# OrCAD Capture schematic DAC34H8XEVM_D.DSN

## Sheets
1 SH1 - DAC: size B; title: DAC34H8X EVM; rev: D; note: DAC
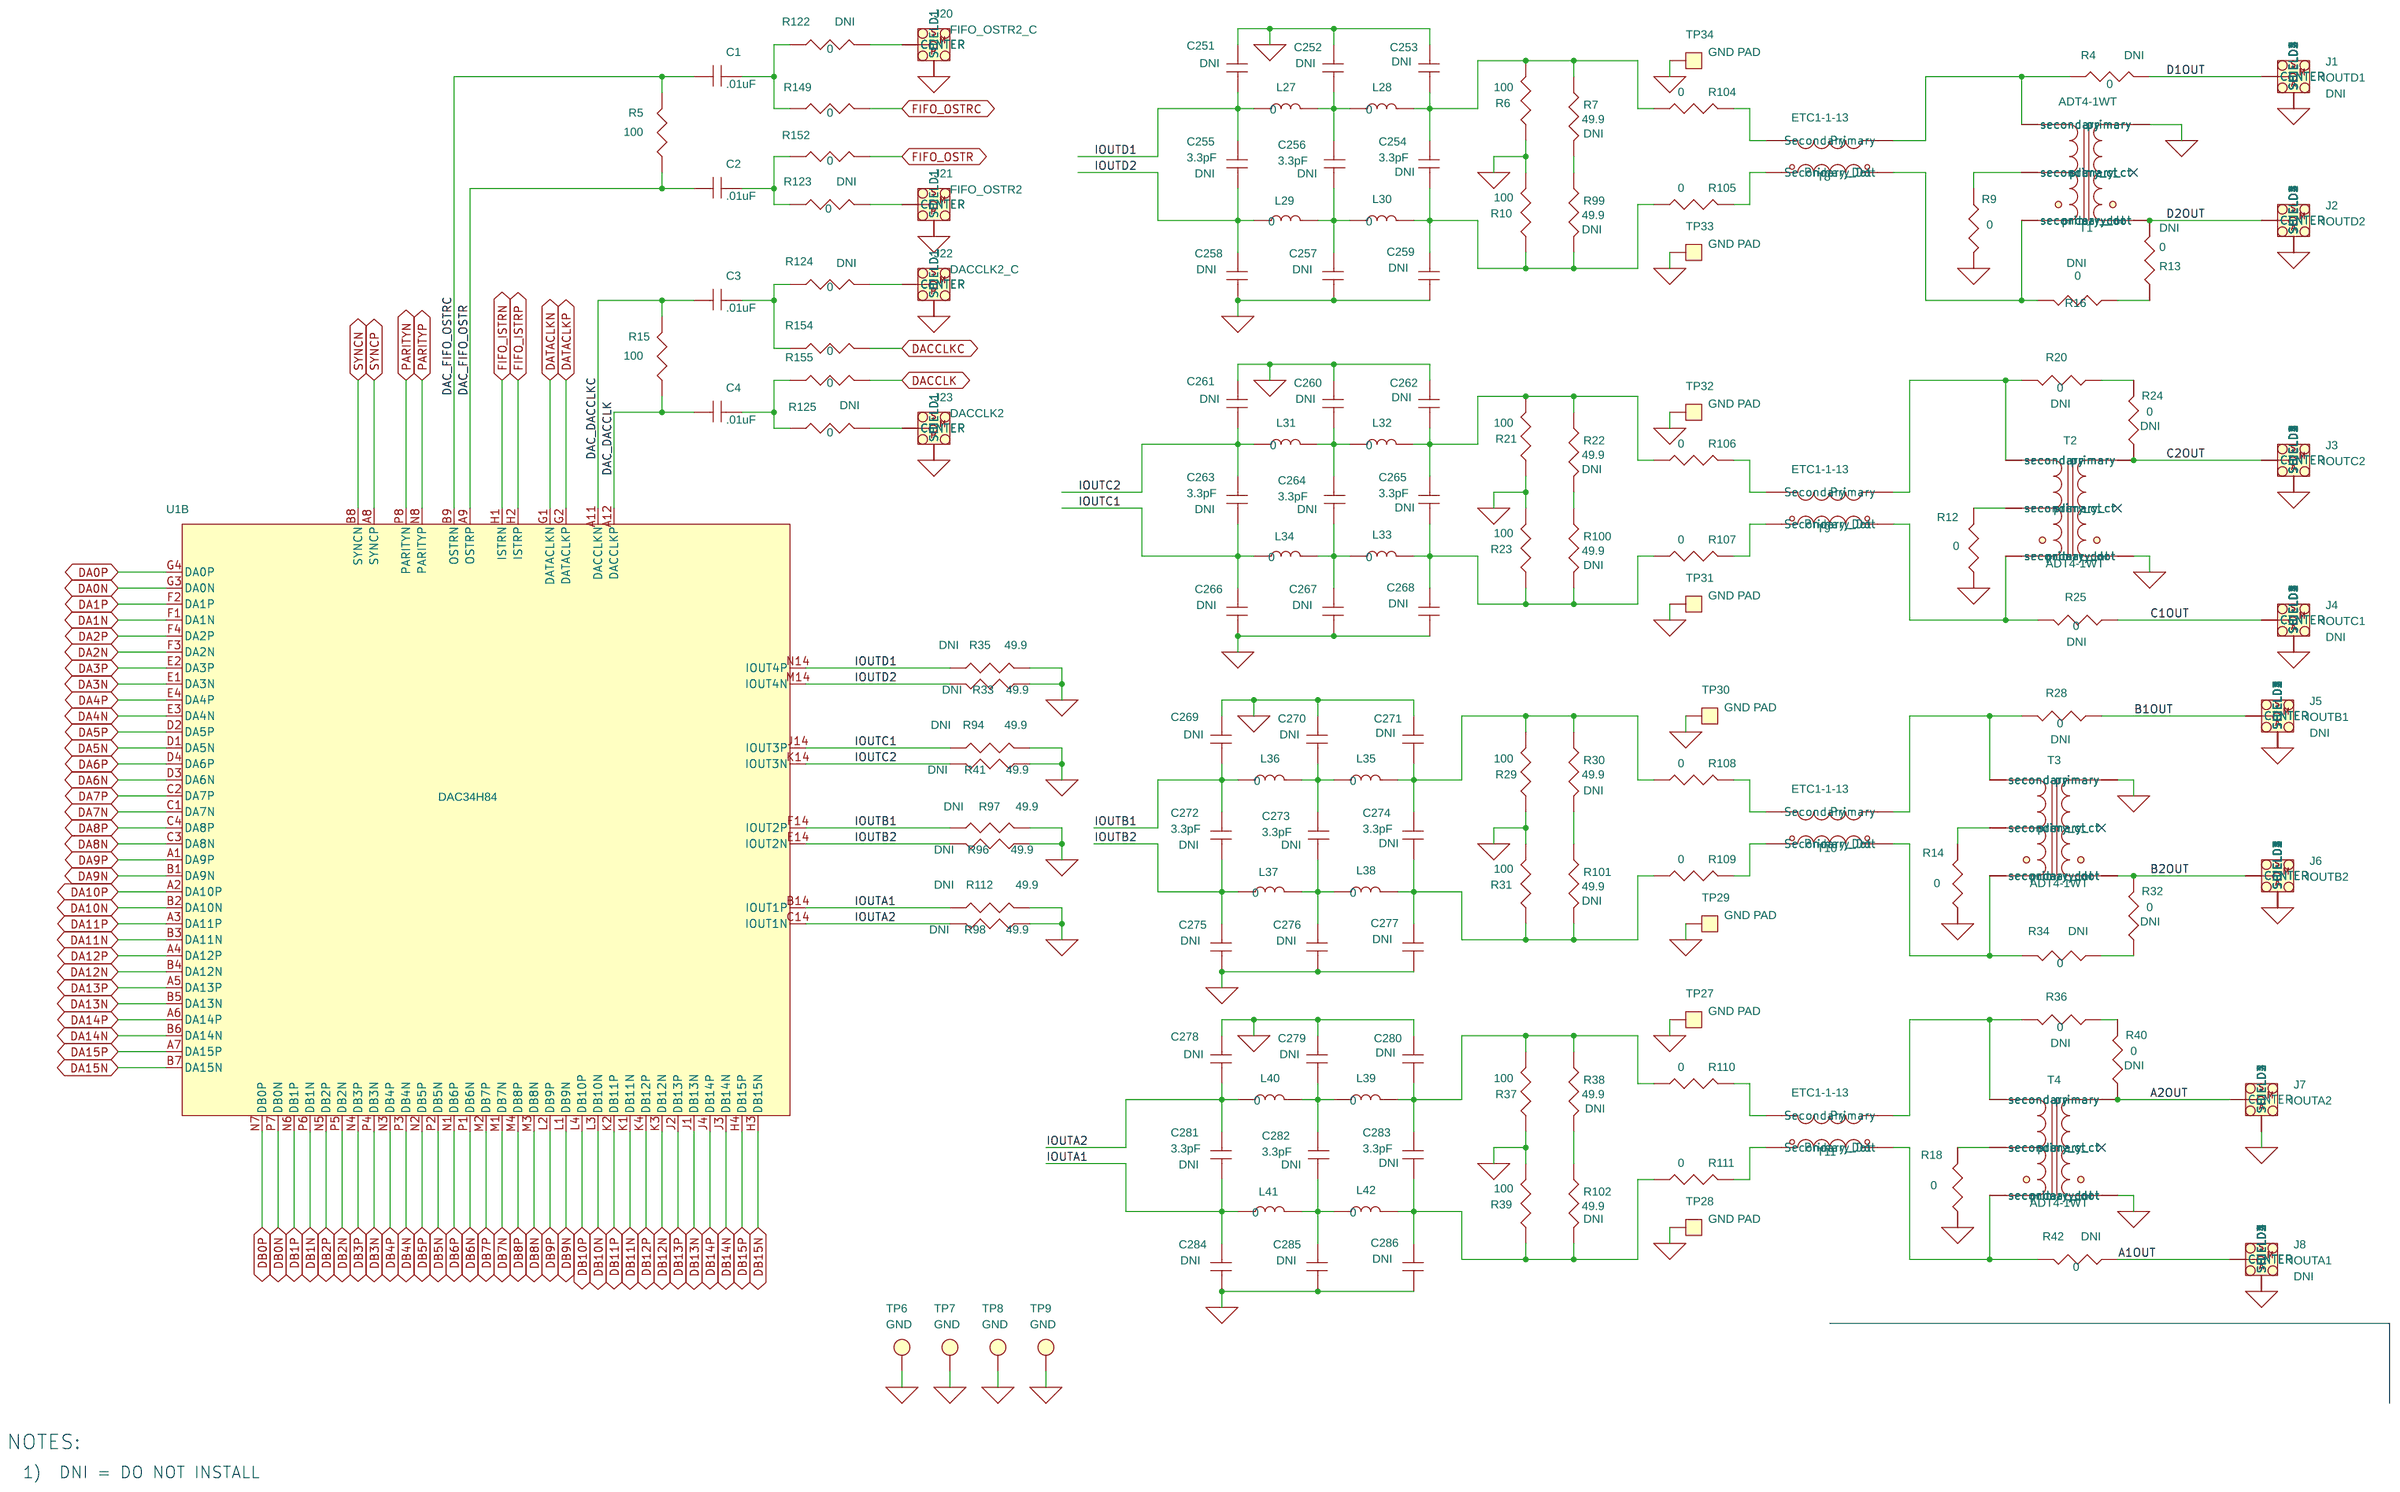
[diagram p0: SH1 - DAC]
2 SH2 - DAC: size B
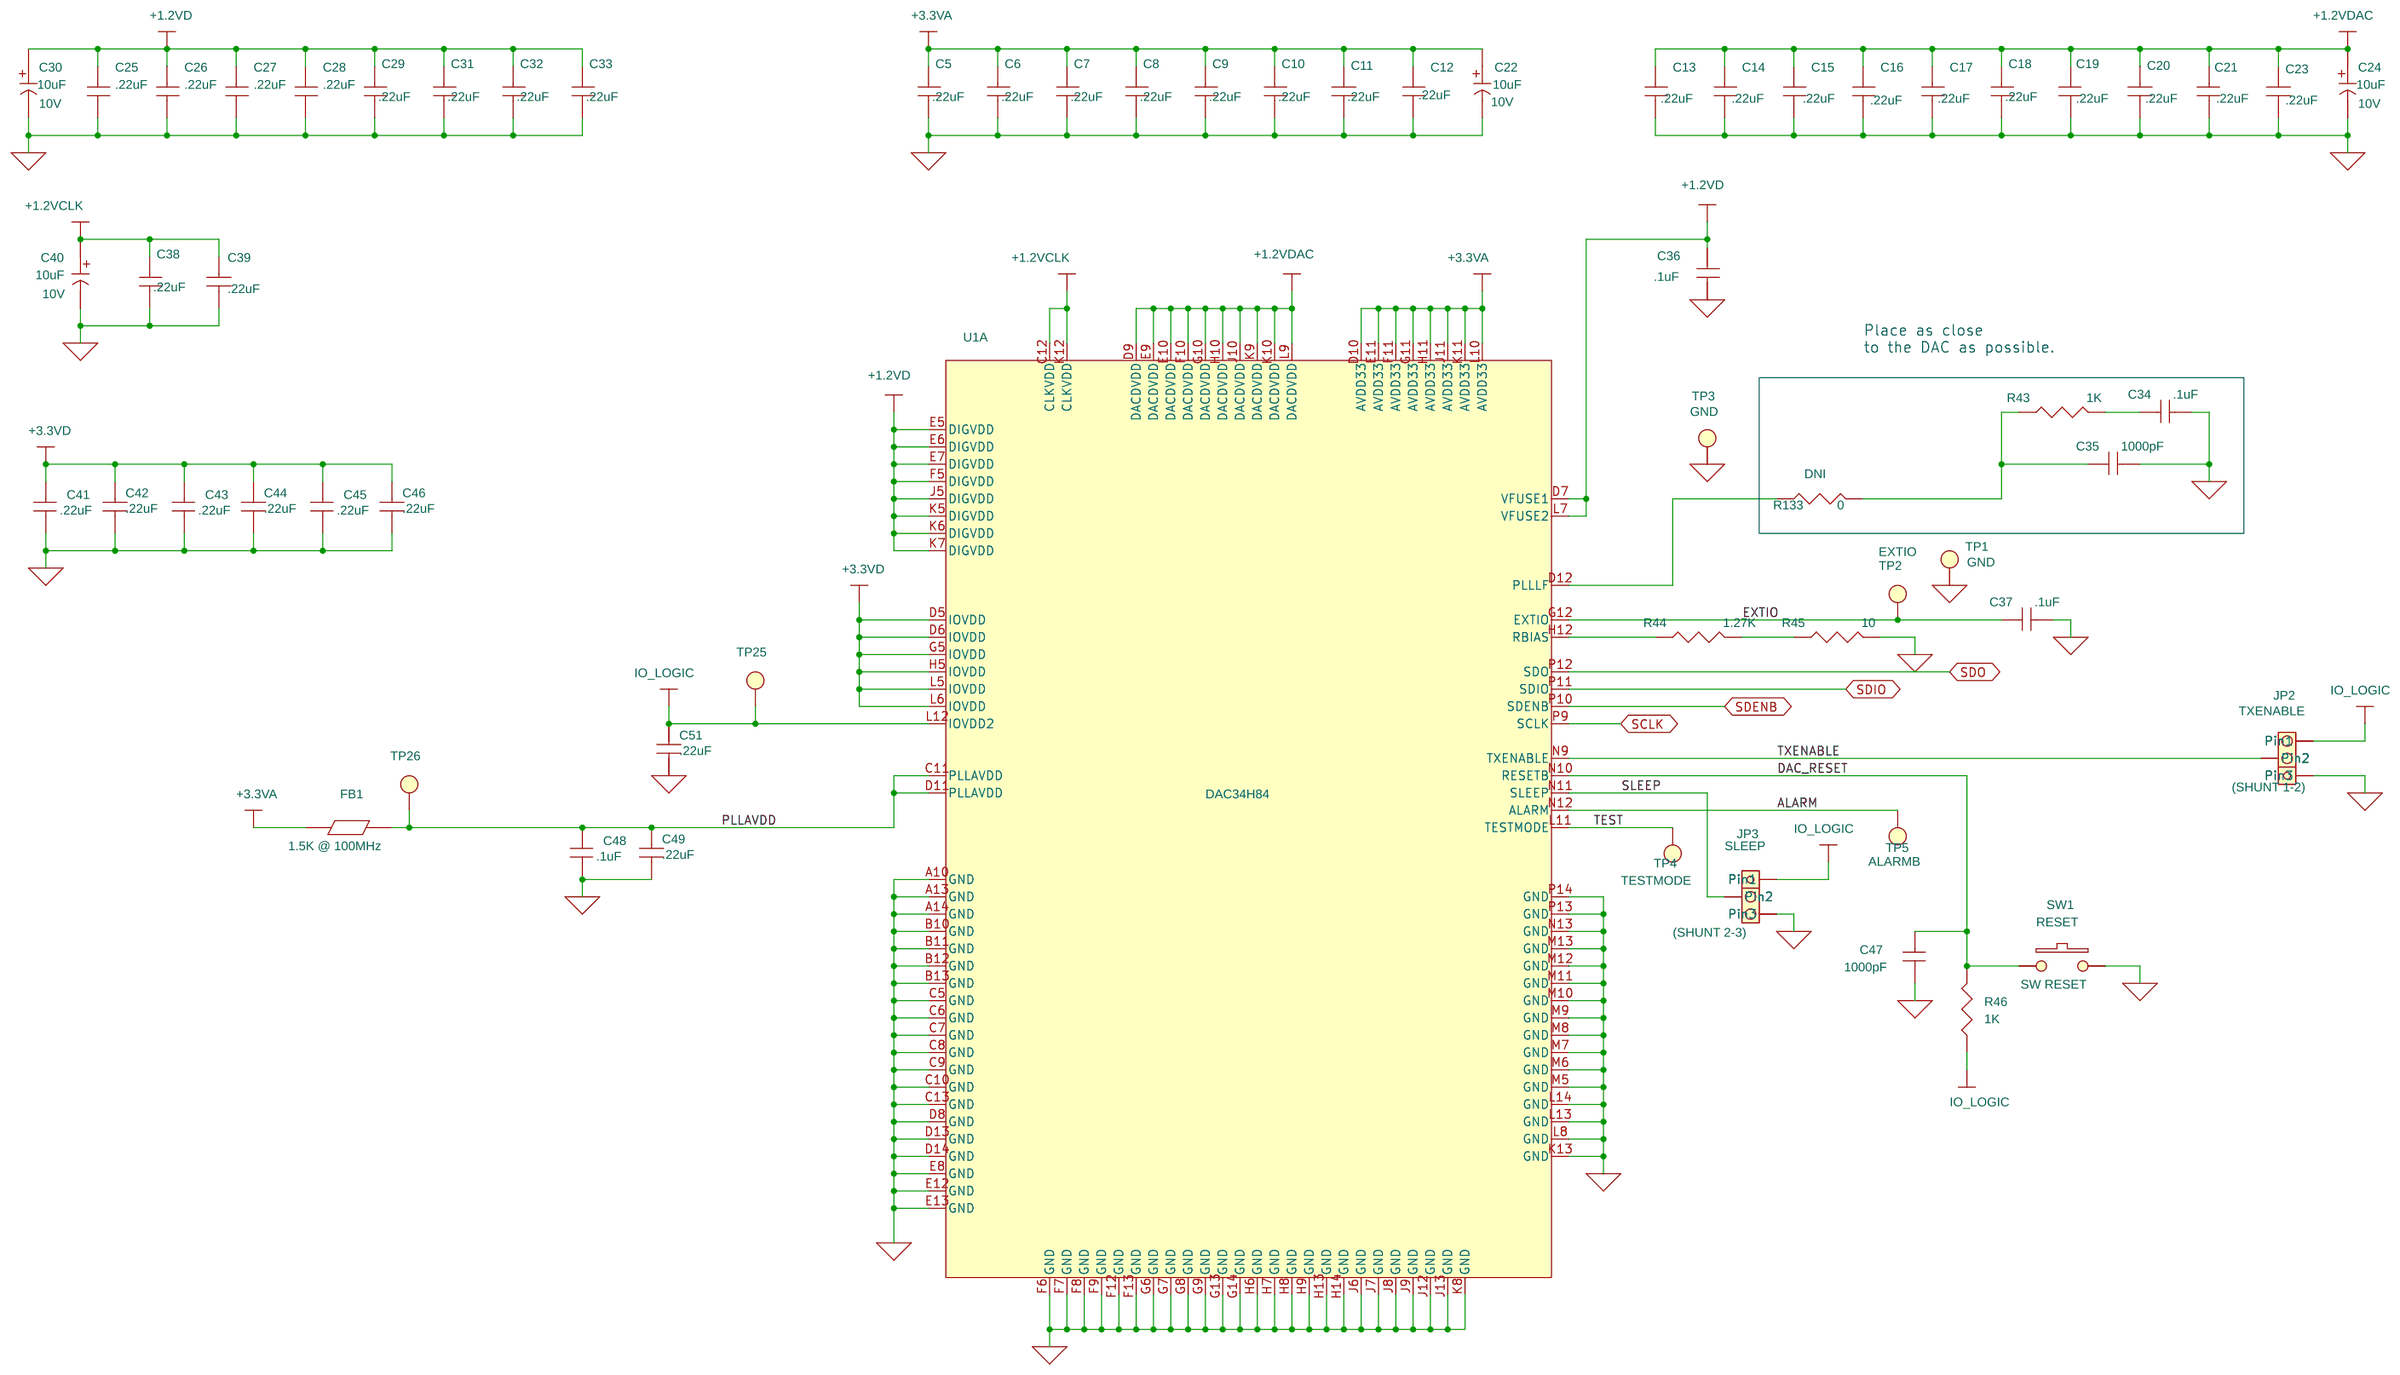
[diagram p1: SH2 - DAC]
3 SH3 - CDC: size B; note: CDC
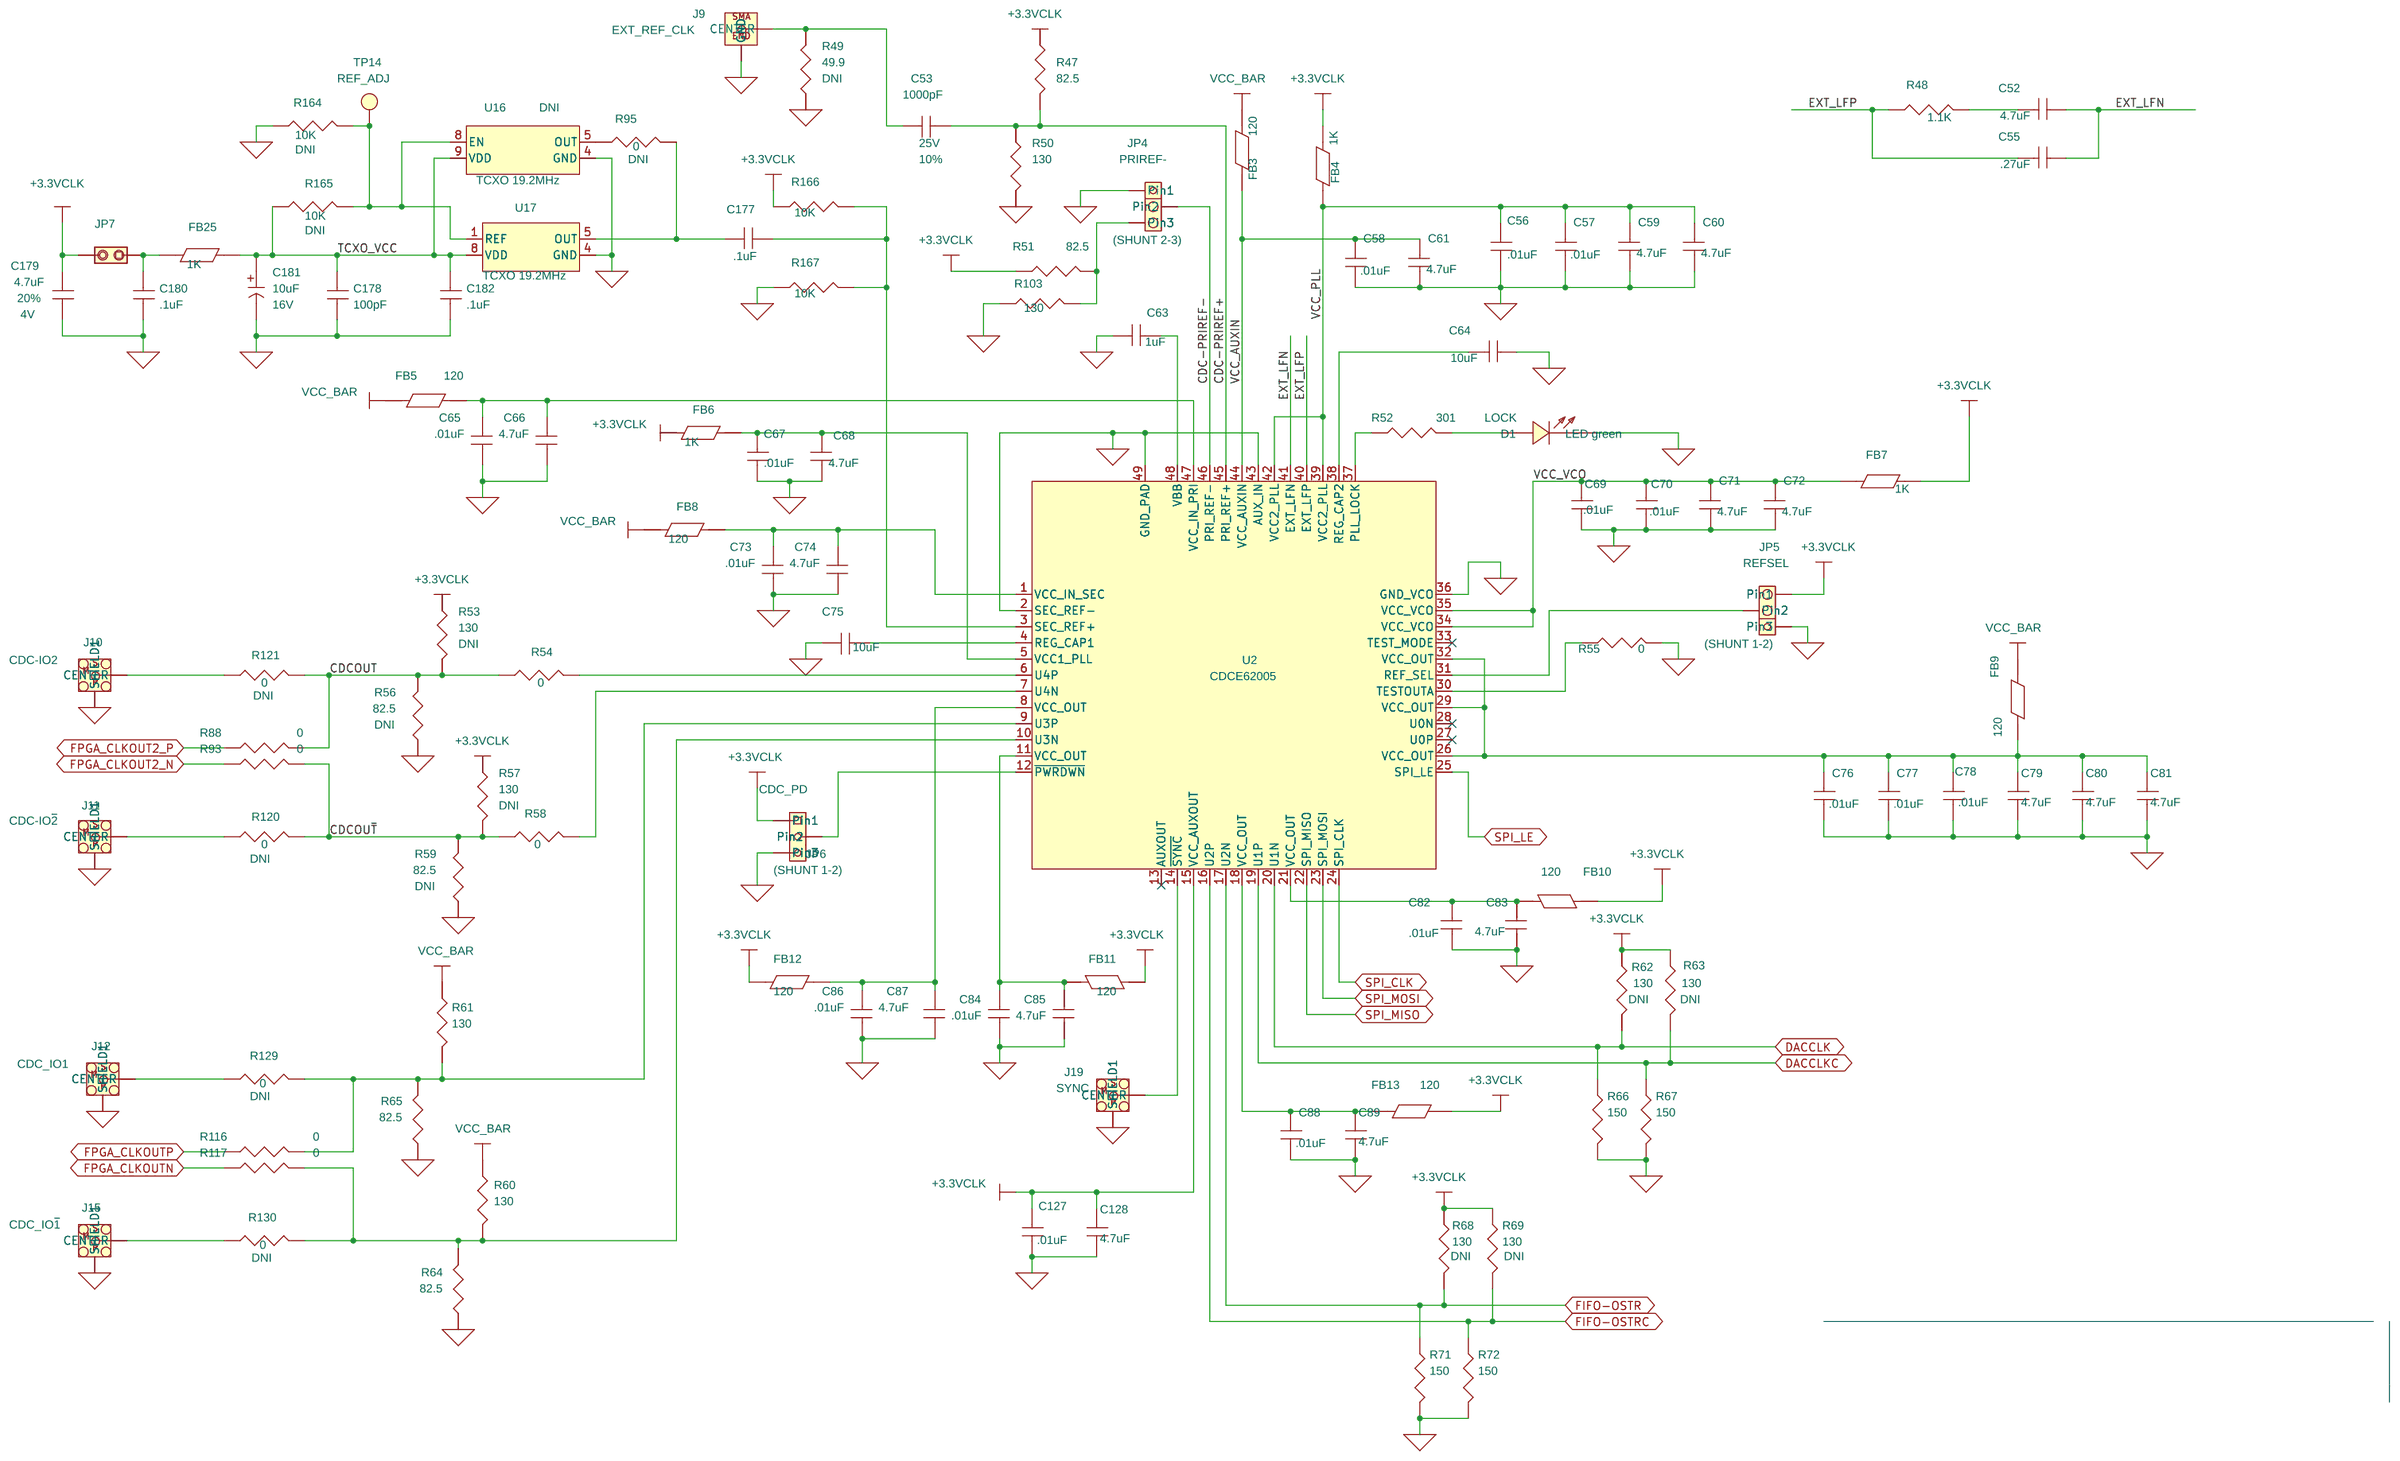
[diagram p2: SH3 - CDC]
4 SH4 - CDC2: size B; note: CDC
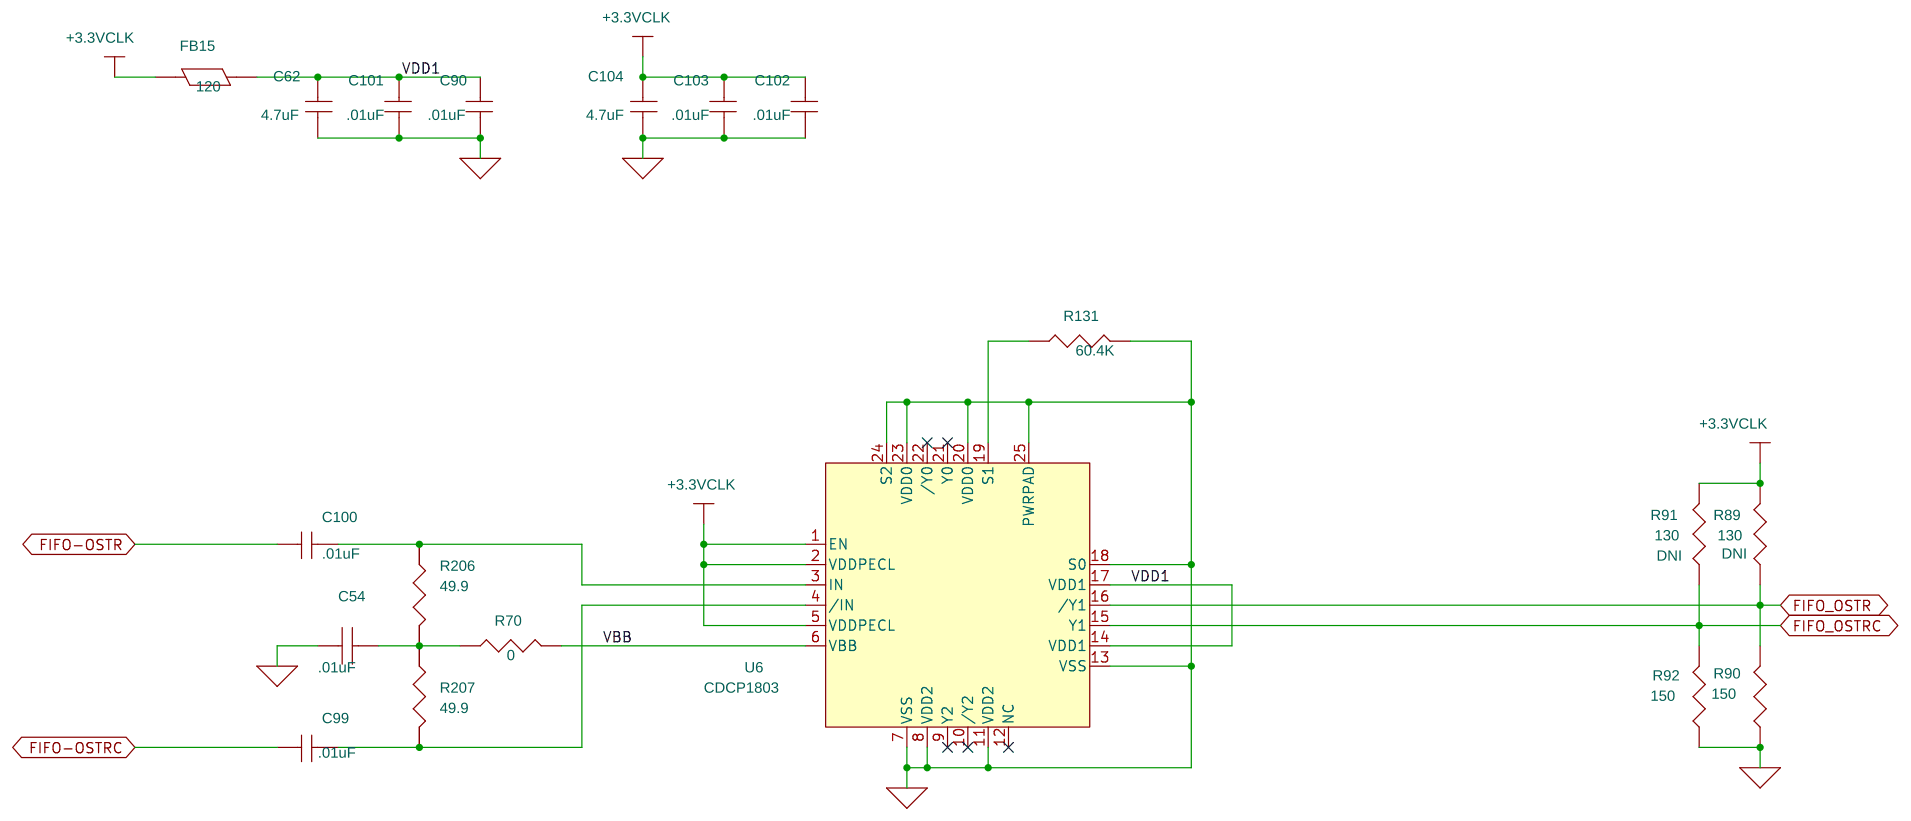
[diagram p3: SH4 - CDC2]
5 SH5 - INTERFACE CONTROL: size B; note: INTERFACE
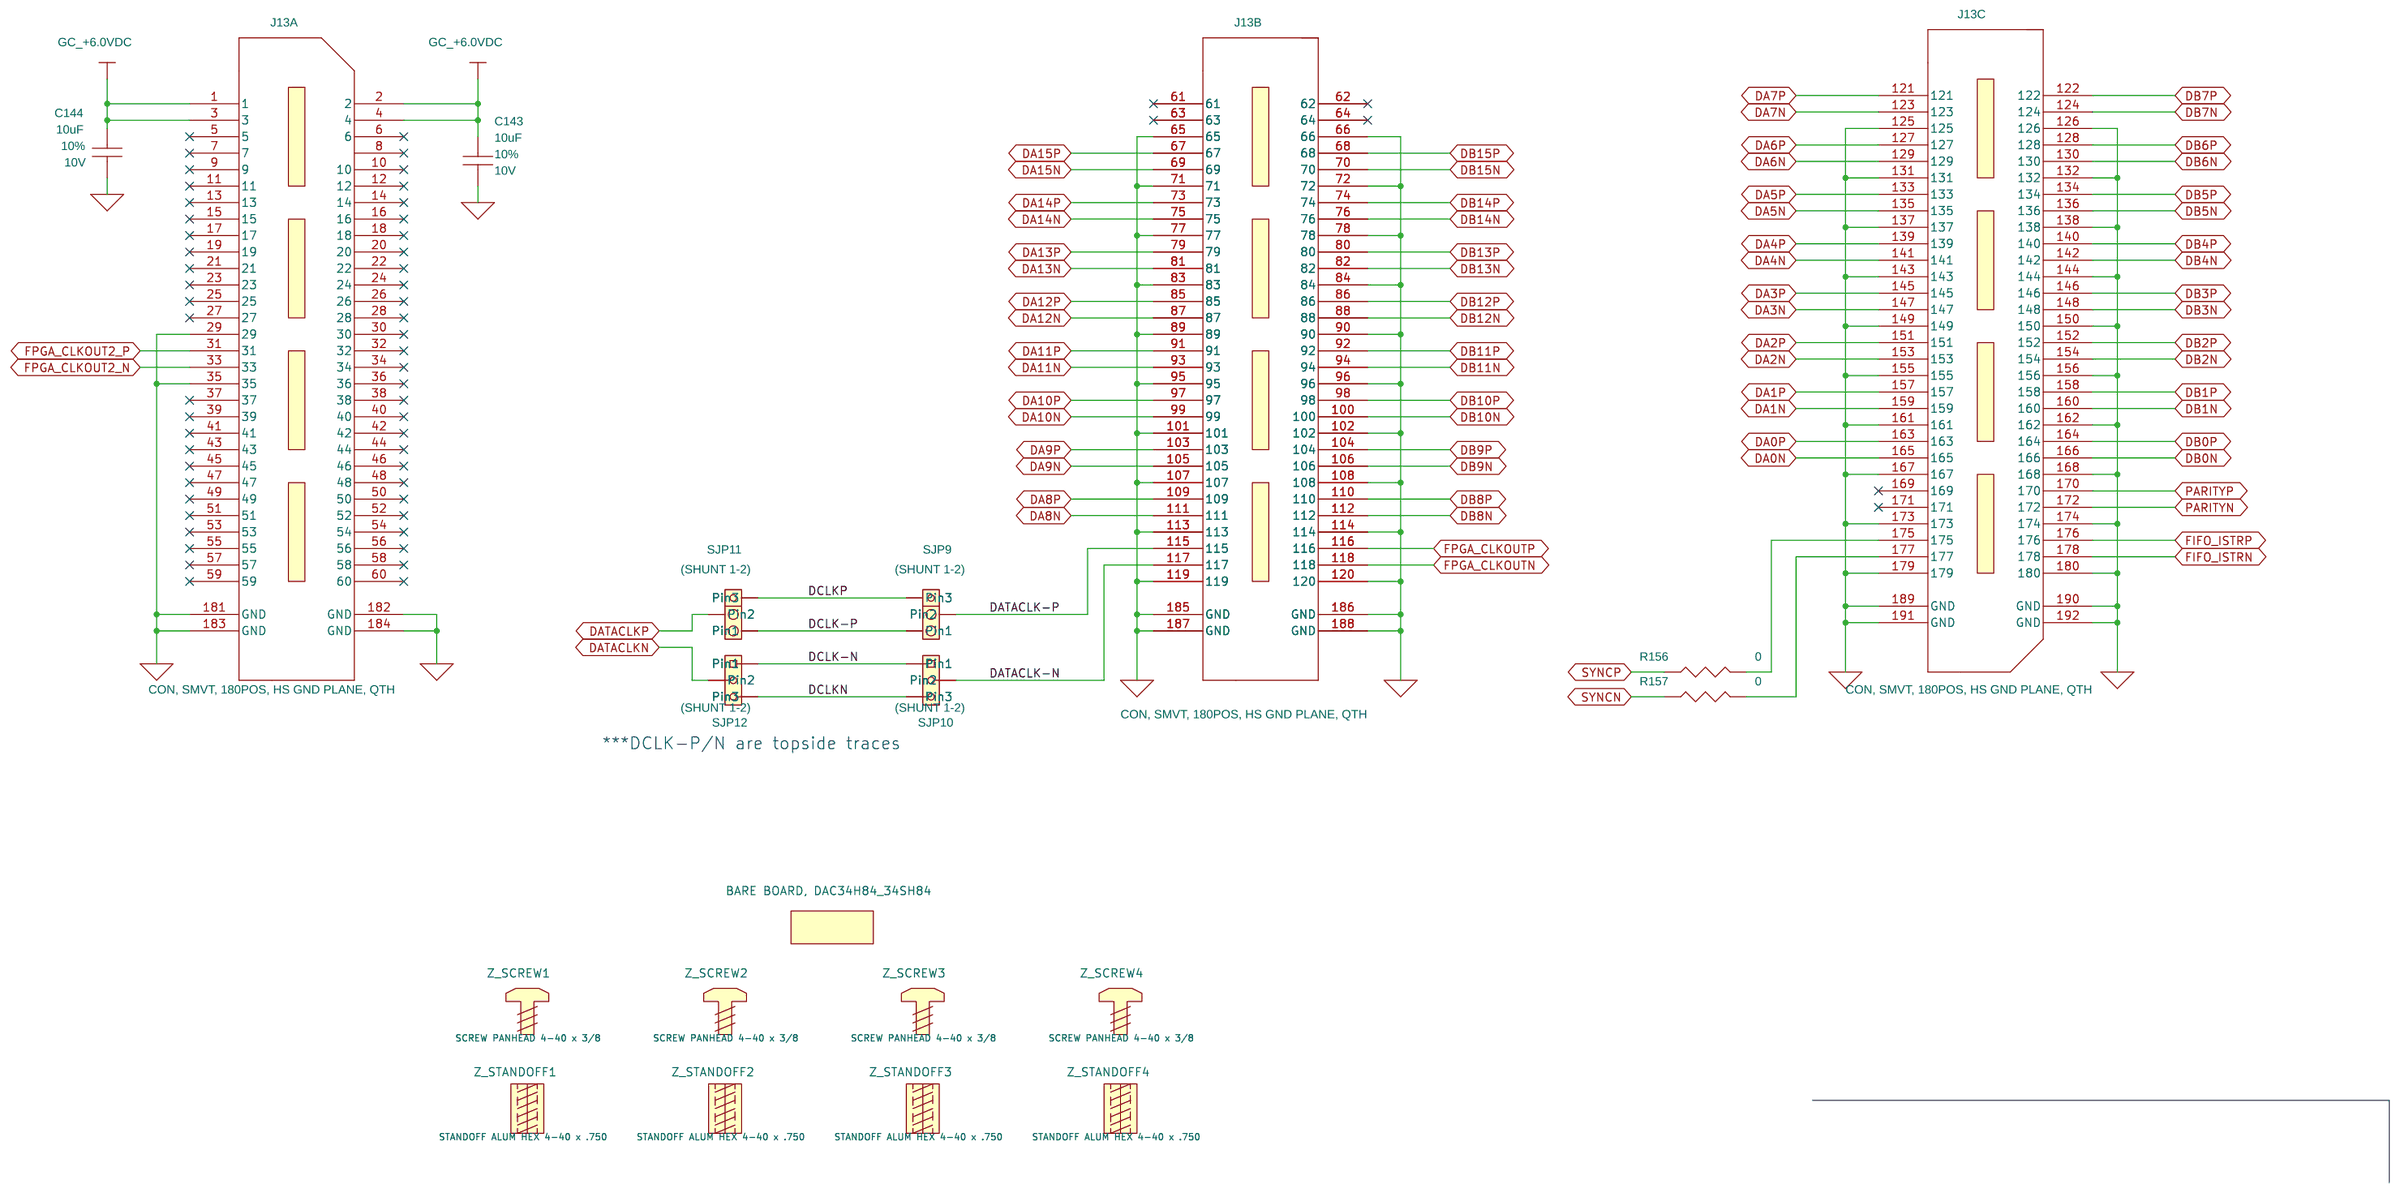
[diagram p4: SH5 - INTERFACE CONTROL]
6 SH6 - USB INTERFACE: size B; note: USB
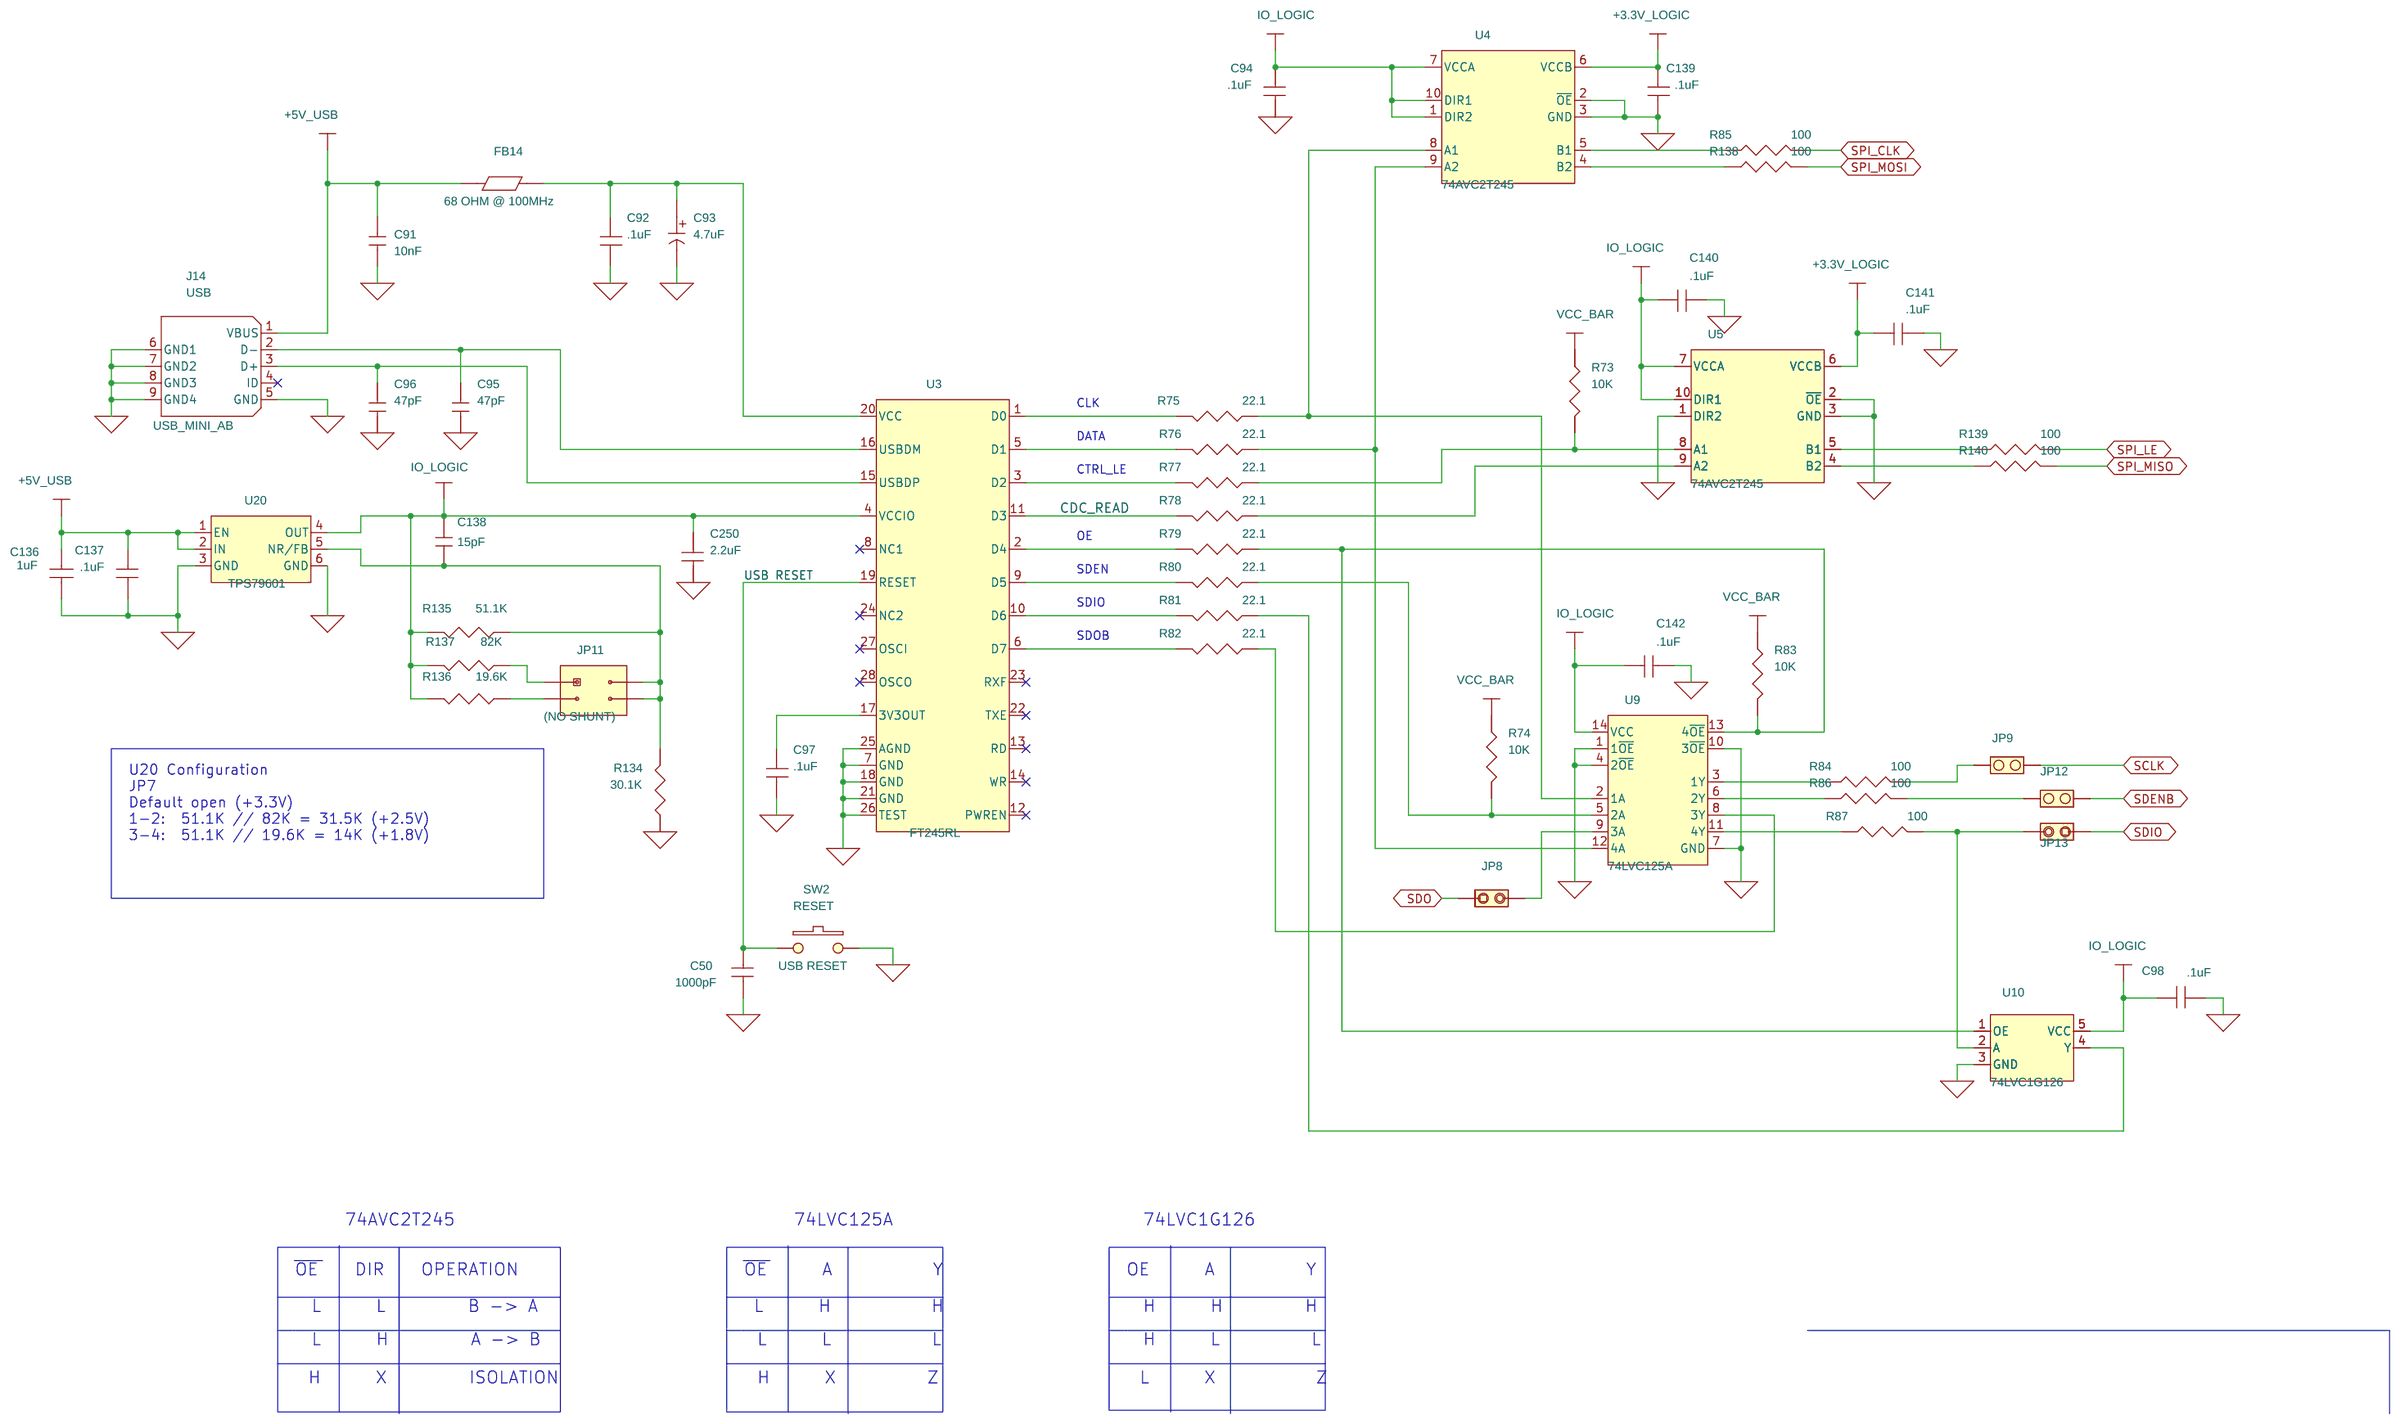
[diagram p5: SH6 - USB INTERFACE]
7 SH7 - POWER DISTRIBUTION: size B
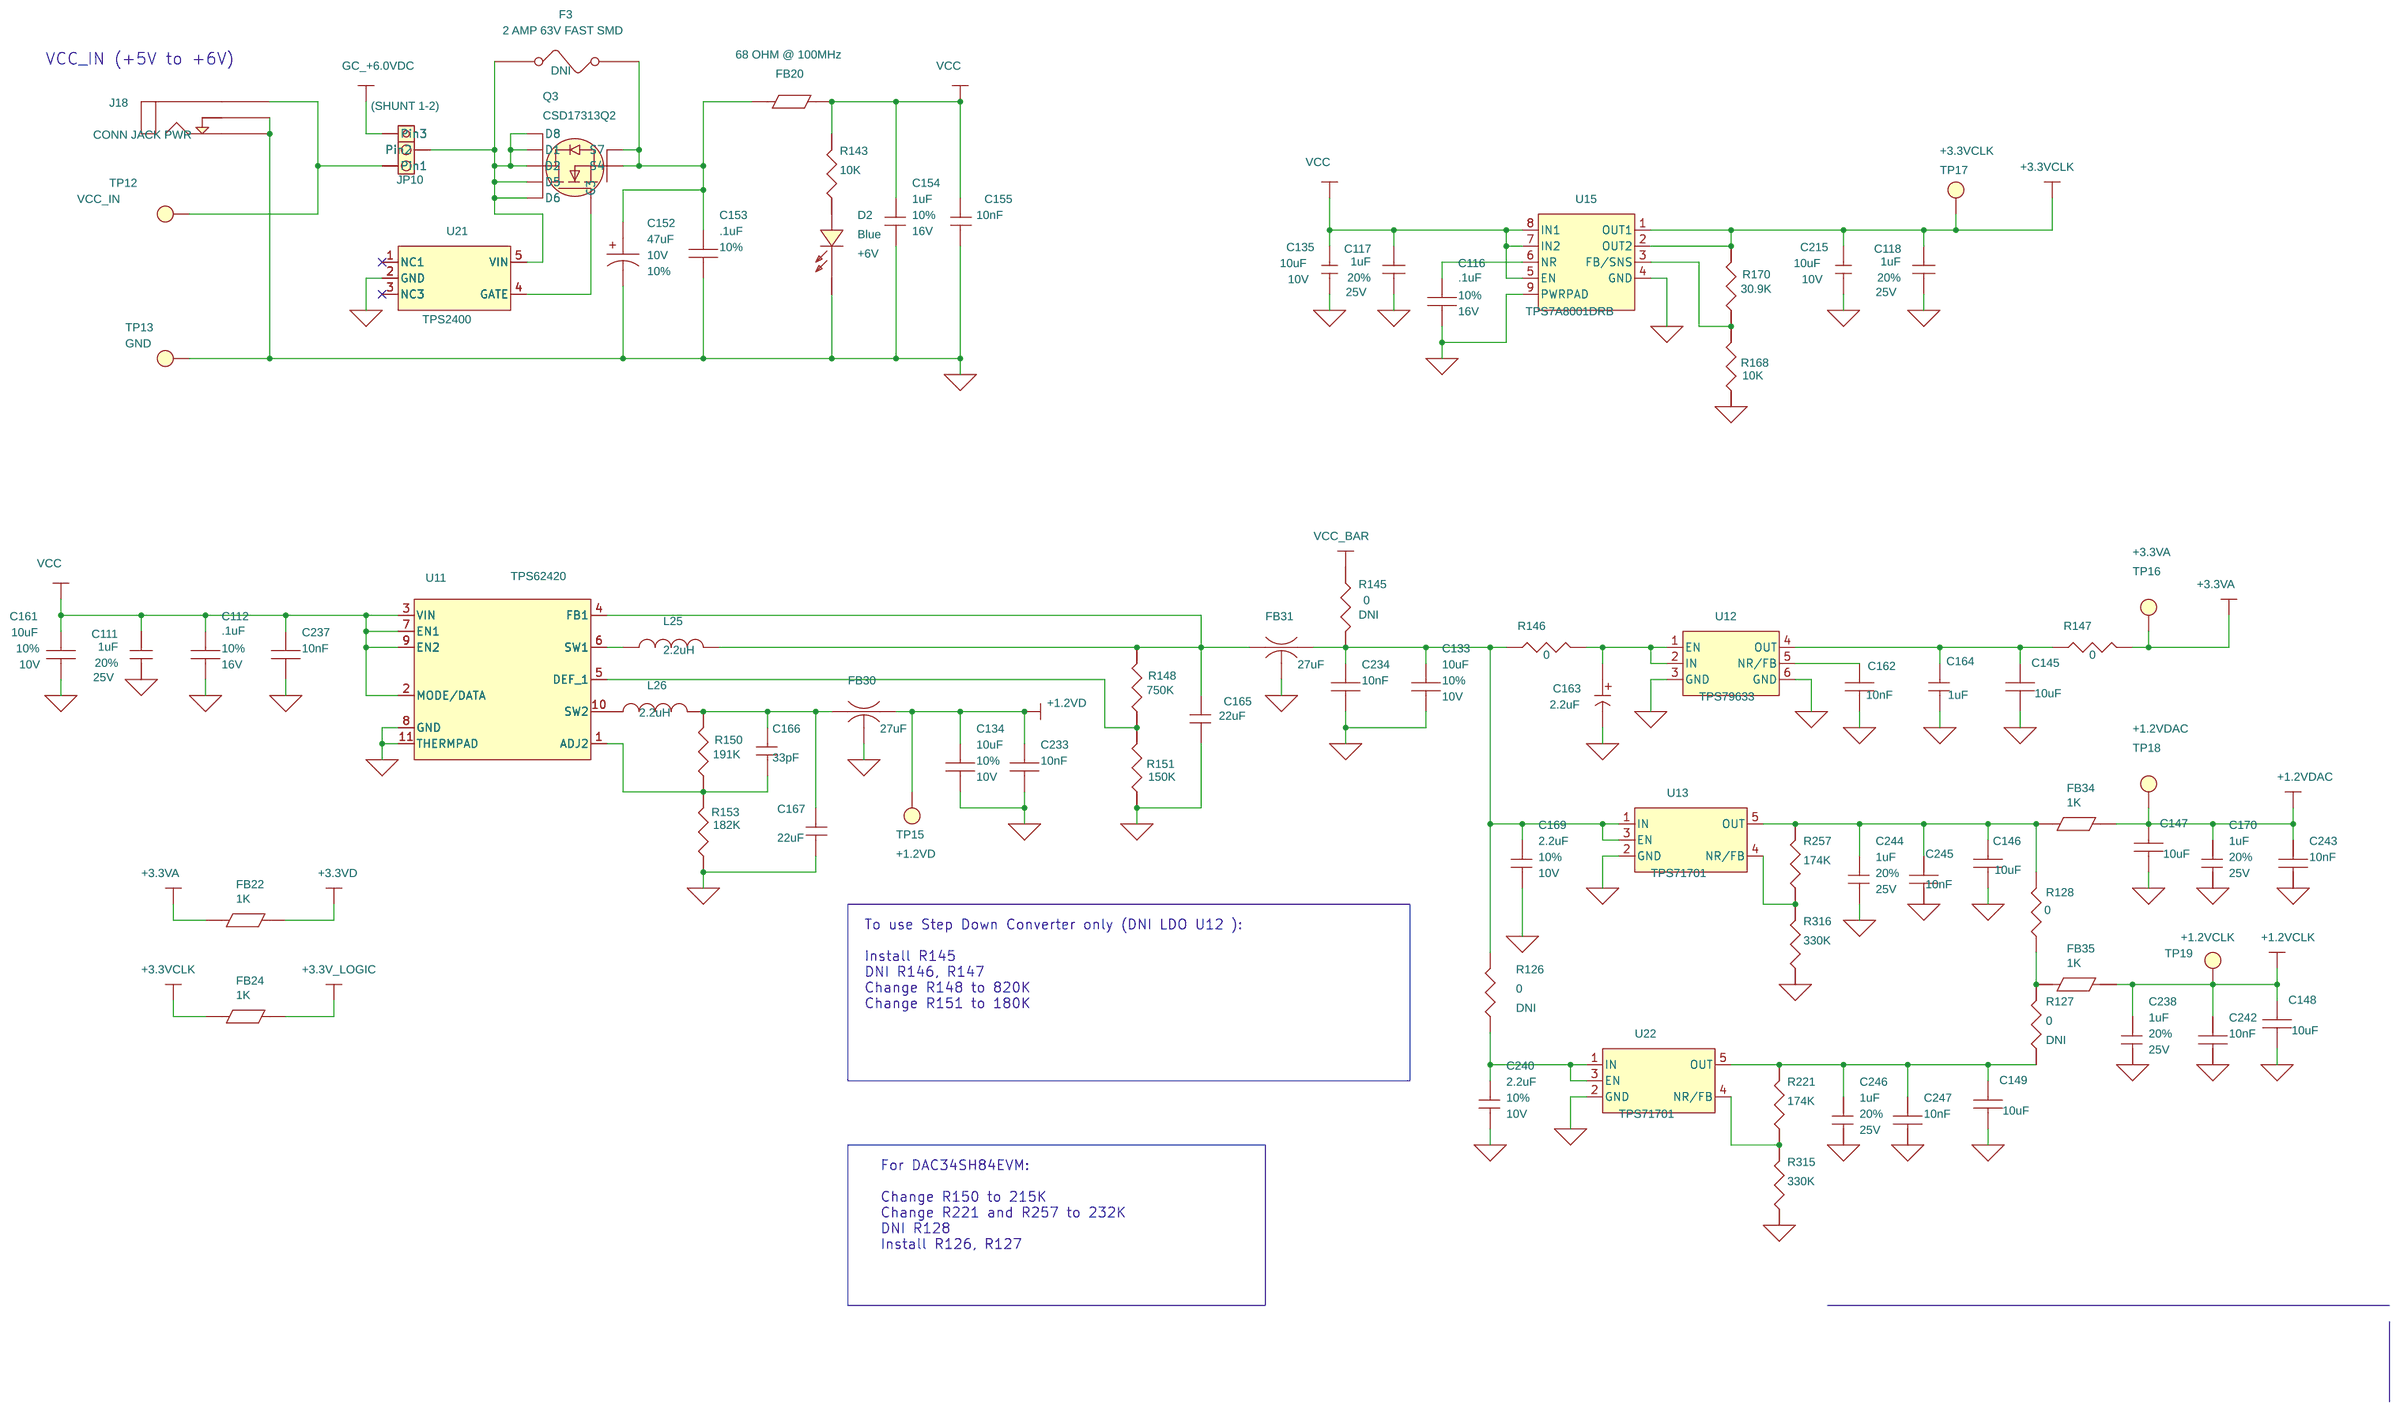
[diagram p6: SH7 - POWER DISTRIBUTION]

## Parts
sheet SH1 - DAC
C1  .01uF  [0402]
C2  .01uF  [0402]
C3  .01uF  [0402]
C4  .01uF  [0402]
C251  CAP NP_1  [0402]
C252  CAP NP_1  [0402]
C253  CAP NP_1  [0402]
C254  3.3pF  [0402]
C255  3.3pF  [0402]
C256  3.3pF  [0402]
C257  CAP NP_1  [0402]
C258  CAP NP_1  [0402]
C259  CAP NP_1  [0402]
C260  CAP NP_1  [0402]
C261  CAP NP_1  [0402]
C262  CAP NP_1  [0402]
C263  3.3pF  [0402]
C264  3.3pF  [0402]
C265  3.3pF  [0402]
C266  CAP NP_1  [0402]
C267  CAP NP_1  [0402]
C268  CAP NP_1  [0402]
C269  CAP NP_1  [0402]
C270  CAP NP_1  [0402]
C271  CAP NP_1  [0402]
C272  3.3pF  [0402]
C273  3.3pF  [0402]
C274  3.3pF  [0402]
C275  CAP NP_1  [0402]
C276  CAP NP_1  [0402]
C277  CAP NP_1  [0402]
C278  CAP NP_1  [0402]
C279  CAP NP_1  [0402]
C280  CAP NP_1  [0402]
C281  3.3pF  [0402]
C282  3.3pF  [0402]
C283  3.3pF  [0402]
C284  CAP NP_1  [0402]
C285  CAP NP_1  [0402]
C286  CAP NP_1  [0402]
J1  SMA_PCB_THVT  [SMA_THVT_312x312]
J2  SMA_PCB_THVT  [SMA_THVT_312x312]
J3  SMA_PCB_THVT  [SMA_THVT_312x312]
J4  SMA_PCB_THVT  [SMA_THVT_312x312]
J5  SMA_PCB_THVT  [SMA_THVT_312x312]
J6  SMA_PCB_THVT  [SMA_THVT_312x312]
J7  SMA_PCB_THVT  [SMA_THVT_312x312]
J8  SMA_PCB_THVT  [SMA_THVT_312x312]
J20  SMP_PCB_SMT  [smp_b120]
J21  SMP_PCB_SMT  [smp_b120]
J22  SMP_PCB_SMT  [smp_b120]
J23  SMP_PCB_SMT  [smp_b120]
L27  0  [0402]
L28  0  [0402]
L29  0  [0402]
L30  0  [0402]
L31  0  [0402]
L32  0  [0402]
L33  0  [0402]
L34  0  [0402]
L35  0  [0402]
L36  0  [0402]
L37  0  [0402]
L38  0  [0402]
L39  0  [0402]
L40  0  [0402]
L41  0  [0402]
L42  0  [0402]
R4  0  [0402]
R5  100  [0402]
R6  100  [0402]
R7  49.9  [0402]
R9  0  [0402]
R10  100  [0402]
R12  0  [0402]
R13  0  [0402]
R14  0  [0402]
R15  100  [0402]
R16  0  [0402]
R18  0  [0402]
R20  0  [0402]
R21  100  [0402]
R22  49.9  [0402]
R23  100  [0402]
R24  0  [0402]
R25  0  [0402]
R28  0  [0402]
R29  100  [0402]
R30  49.9  [0402]
R31  100  [0402]
R32  0  [0402]
R33  49.9  [0201]
R34  0  [0402]
R35  49.9  [0201]
R36  0  [0402]
R37  100  [0402]
R38  49.9  [0402]
R39  100  [0402]
R40  0  [0402]
R41  49.9  [0201]
R42  0  [0402]
R94  49.9  [0201]
R96  49.9  [0201]
R97  49.9  [0201]
R98  49.9  [0201]
R99  49.9  [0402]
R100  49.9  [0402]
R101  49.9  [0402]
R102  49.9  [0402]
R104  0  [0402]
R105  0  [0402]
R106  0  [0402]
R107  0  [0402]
R108  0  [0402]
R109  0  [0402]
R110  0  [0402]
R111  0  [0402]
R112  49.9  [0201]
R122  0  [0402]
R123  0  [0402]
R124  0  [0402]
R125  0  [0402]
R149  0  [0402]
R152  0  [0402]
R154  0  [0402]
R155  0  [0402]
T1  ADT4-1WT  [TFMR_6_RF_DUAL_FOOTPRINT]
T2  ADT4-1WT  [TFMR_6_RF_DUAL_FOOTPRINT]
T3  ADT4-1WT  [TFMR_6_RF_DUAL_FOOTPRINT]
T4  ADT4-1WT  [TFMR_6_RF_DUAL_FOOTPRINT]
T8  ETC1-1-13  [TFMR_6_RF_DUAL_FOOTPRINT]
T9  ETC1-1-13  [TFMR_6_RF_DUAL_FOOTPRINT]
T10  ETC1-1-13  [TFMR_6_RF_DUAL_FOOTPRINT]
T11  ETC1-1-13  [TFMR_6_RF_DUAL_FOOTPRINT]
TP6  Testloop_Black  [testpoint_62dia]
TP7  Testloop_Black  [testpoint_62dia]
TP8  Testloop_Black  [testpoint_62dia]
TP9  Testloop_Black  [testpoint_62dia]
TP27  GND PAD  [testpad20_30]
TP28  GND PAD  [testpad20_30]
TP29  GND PAD  [testpad20_30]
TP30  GND PAD  [testpad20_30]
TP31  GND PAD  [testpad20_30]
TP32  GND PAD  [testpad20_30]
TP33  GND PAD  [testpad20_30]
TP34  GND PAD  [testpad20_30]
U1  DAC34H84  [BGA14X14_PT8MM]  (sections A,B)
sheet SH2 - DAC
C5  .22uF  [0201]
C6  .22uF  [0201]
C7  .22uF  [0201]
C8  .22uF  [0201]
C9  .22uF  [0201]
C10  .22uF  [0201]
C11  .22uF  [0201]
C12  .22uF  [0201]
C13  .22uF  [0201]
C14  .22uF  [0201]
C15  .22uF  [0201]
C16  .22uF  [0201]
C17  .22uF  [0201]
C18  .22uF  [0201]
C19  .22uF  [0201]
C20  .22uF  [0201]
C21  .22uF  [0201]
C22  10uF  [tant_a]
C23  .22uF  [0201]
C24  10uF  [tant_a]
C25  .22uF  [0201]
C26  .22uF  [0201]
C27  .22uF  [0201]
C28  .22uF  [0201]
C29  .22uF  [0201]
C30  10uF  [tant_a]
C31  .22uF  [0201]
C32  .22uF  [0201]
C33  .22uF  [0201]
C34  .1uF  [0402]
C35  1000pF  [0402]
C36  .1uF  [0201]
C37  .1uF  [0402]
C38  .22uF  [0201]
C39  .22uF  [0201]
C40  10uF  [tant_a]
C41  .22uF  [0201]
C42  .22uF  [0201]
C43  .22uF  [0201]
C44  .22uF  [0201]
C45  .22uF  [0201]
C46  .22uF  [0201]
C47  1000pF  [0402]
C48  .1uF  [0201]
C49  .22uF  [0201]
C51  .22uF  [0201]
FB1  1.5K @ 100MHz  [0603]
JP2  Jumper_1x3_100_430L  [HDR_THVT_1x3_100_M]
JP3  Jumper_1x3_100_430L  [HDR_THVT_1x3_100_M]
R43  1K  [0402]
R44  1.27K  [0402]
R45  10  [0402]
R46  1K  [0402]
R133  0  [0402]
SW1  SW RESET  [SW_SMVT_RESET]
TP1  Testloop_Black  [testpoint_62dia]
TP2  Testloop_White  [testpoint_62dia]
TP3  Testloop_Black  [TP_THVT_060_RND]
TP4  Testloop_White  [testpoint_62dia]
TP5  Testloop_White  [testpoint_62dia]
TP25  Testloop_White  [testpoint_62dia]
TP26  Testloop_White  [testpoint_62dia]
Z_SH-H2  SHUNT-HEADER
Z_SH-H3  SHUNT-HEADER
sheet SH3 - CDC
C52  4.7uF  [0603]
C53  1000pF  [0402]
C55  .27uF  [0603]
C56  .01uF  [0201]
C57  .01uF  [0201]
C58  .01uF  [0201]
C59  4.7uF  [0603]
C60  4.7uF  [0603]
C61  4.7uF  [0603]
C63  1uF  [0402]
C64  10uF  [0805]
C65  .01uF  [0201]
C66  4.7uF  [0603]
C67  .01uF  [0201]
C68  4.7uF  [0603]
C69  .01uF  [0201]
C70  .01uF  [0201]
C71  4.7uF  [0603]
C72  4.7uF  [0603]
C73  .01uF  [0201]
C74  4.7uF  [0603]
C75  10uF  [0805]
C76  .01uF  [0201]
C77  .01uF  [0201]
C78  .01uF  [0201]
C79  4.7uF  [0603]
C80  4.7uF  [0603]
C81  4.7uF  [0603]
C82  .01uF  [0201]
C83  4.7uF  [0603]
C84  .01uF  [0201]
C85  4.7uF  [0603]
C86  .01uF  [0201]
C87  4.7uF  [0603]
C88  .01uF  [0201]
C89  4.7uF  [0603]
C127  .01uF  [0201]
C128  4.7uF  [0603]
C177  .1uF  [0402]
C178  100pF  [0402]
C179  4.7uF  [0402]
C180  .1uF  [0402]
C181  10uF  [tant_a]
C182  .1uF  [0402]
D1  LED green  [LED_0805]
FB3  120  [0402]
FB4  1K  [0402]
FB5  120  [0402]
FB6  1K  [0402]
FB7  1K  [0402]
FB8  120  [0402]
FB9  120  [0402]
FB10  120  [0402]
FB11  120  [0402]
FB12  120  [0402]
FB13  120  [0402]
FB25  1K  [0402]
J9  SMA_END_JACK_RND  [SMA_SMEL_218x247_096]
J10  SMP_PCB_SMT  [smp_b120]
J11  SMP_PCB_SMT  [smp_b120]
J12  SMP_PCB_SMT  [smp_b120]
J15  SMP_PCB_SMT  [smp_b120]
J19  SMP_PCB_SMT  [smp_b120]
JP4  Jumper_1x3_100_430L  [HDR_THVT_1x3_100_M]
JP5  Jumper_1x3_100_430L  [HDR_THVT_1x3_100_M]
JP6  Jumper_1x3_100_430L  [HDR_THVT_1x3_100_M]
JP7  HEADER_1x2_100_430L  [HDR_THVT_1x2_100_M]
R47  82.5  [0402]
R48  1.1K  [0402]
R49  49.9  [0402]
R50  130  [0402]
R51  82.5  [0402]
R52  301  [0402]
R53  130  [0402]
R54  0  [0402]
R55  0  [0402]
R56  82.5  [0402]
R57  130  [0402]
R58  0  [0402]
R59  82.5  [0402]
R60  130  [0402]
R61  130  [0402]
R62  130  [0402]
R63  130  [0402]
R64  82.5  [0402]
R65  82.5  [0402]
R66  150  [0402]
R67  150  [0402]
R68  130  [0402]
R69  130  [0402]
R71  150  [0402]
R72  150  [0402]
R88  0  [0402]
R93  0  [0402]
R95  0  [0402]
R103  130  [0402]
R116  0  [0402]
R117  0  [0402]
R120  0  [0402]
R121  0  [0402]
R129  0  [0402]
R130  0  [0402]
R164  10K  [0402]
R165  10K  [0402]
R166  10K  [0402]
R167  10K  [0402]
TP14  Testloop_White  [testpoint_62dia]
U2  CDCE62005  [QFN48_RGZ_RTC]
U16  TCXO 19.2MHz  [SMD_XTAL_7X5MM_D75Aseries]
U17  TCXO 19.2MHz  [OSC_4_SM_460x386]
Z_SH-H4  SHUNT-HEADER  [0603]
Z_SH-H5  SHUNT-HEADER
Z_SH-H6  SHUNT-HEADER
Z_SH-H7  SHUNT-HEADER
sheet SH4 - CDC2
C54  .01uF  [0402]
C62  4.7uF  [0603]
C90  .01uF  [0402]
C99  .01uF  [0402]
C100  .01uF  [0402]
C101  .01uF  [0402]
C102  .01uF  [0402]
C103  .01uF  [0402]
C104  4.7uF  [0603]
FB15  120  [0402]
R70  0  [0402]
R89  130  [0402]
R90  150  [0402]
R91  130  [0402]
R92  150  [0402]
R131  60.4K  [0402]
R206  49.9  [0402]
R207  49.9  [0402]
U6  CDCP1803  [qfn24_rge_rtw]
sheet SH5 - INTERFACE CONTROL
C143  10uF  [0805]
C144  10uF  [0805]
J13  CON, SMVT, 180POS, HS GND PLANE, QTH  [CON_SMVT_180POS_QTH_SAMTEC_RT1]  (sections A,B,C)
R156  0  [0402]
R157  0  [0402]
SJP9  SMT Jumper_1x3  [0201_smd_jumper3x1]
SJP10  SMT Jumper_1x3  [0201_smd_jumper3x1]
SJP11  SMT Jumper_1x3  [0201_smd_jumper3x1]
SJP12  SMT Jumper_1x3  [0201_smd_jumper3x1]
Z_BOARD1  BARE BOARD, DAC34H84_34SH84
Z_SCREW1  SCREW PANHEAD 4-40 x 3/8
Z_SCREW2  SCREW PANHEAD 4-40 x 3/8
Z_SCREW3  SCREW PANHEAD 4-40 x 3/8
Z_SCREW4  SCREW PANHEAD 4-40 x 3/8
Z_SH-H8  0 Ohm  [0402]
Z_SH-H9  0 Ohm
Z_SH-H10  0 Ohm
Z_SH-H11  0 Ohm
Z_STANDOFF1  STANDOFF ALUM HEX 4-40 x .750
Z_STANDOFF2  STANDOFF ALUM HEX 4-40 x .750
Z_STANDOFF3  STANDOFF ALUM HEX 4-40 x .750
Z_STANDOFF4  STANDOFF ALUM HEX 4-40 x .750
sheet SH6 - USB INTERFACE
C50  1000pF  [0402]
C91  10nF  [0402]
C92  .1uF  [0402]
C93  4.7uF  [tant_a]
C94  .1uF  [0402]
C95  47pF  [0402]
C96  47pF  [0402]
C97  .1uF  [0402]
C98  .1uF  [0402]
C136  1uF  [0402]
C137  .1uF  [0402]
C138  15pF  [0402]
C139  .1uF  [0402]
C140  .1uF  [0402]
C141  .1uF  [0402]
C142  .1uF  [0402]
C250  2.2uF  [0603]
FB14  68 OHM @ 100MHz  [1206]
J14  USB_MINI_AB  [CON_SMRT_USBMNE20_F]
JP8  HEADER_1x2_100_430L  [HDR_THVT_1x2_100_M]
JP9  HEADER_1x2_100_430L  [HDR_THVT_1x2_100_M]
JP11  JUMPER_2X2  [HDR2X2_100CTR]
JP12  HEADER_1x2_100_430L  [HDR_THVT_1x2_100_M]
JP13  HEADER_1x2_100_430L  [HDR_THVT_1x2_100_M]
R73  10K  [0402]
R74  10K  [0402]
R75  22.1  [0402]
R76  22.1  [0402]
R77  22.1  [0402]
R78  22.1  [0402]
R79  22.1  [0402]
R80  22.1  [0402]
R81  22.1  [0402]
R82  22.1  [0402]
R83  10K  [0402]
R84  100  [0402]
R85  100  [0402]
R86  100  [0402]
R87  100  [0402]
R134  30.1K  [0402]
R135  51.1K  [0402]
R136  19.6K  [0402]
R137  82K  [0402]
R138  100  [0402]
R139  100  [0402]
R140  100  [0402]
SW2  USB RESET  [SW_SMVT_RESET]
U3  FT245RL  [ssop_28_413x220_26]
U4  74AVC2T245  [QFN10_RSW]
U5  74AVC2T245  [QFN10_RSW]
U9  74LVC125A  [TSSOP_14_201X177_26]
U10  74LVC1G126  [DBV5]
U20  TPS79601  [SOT_223_6_TG]
Z_SH-H13  SHUNT-HEADER
Z_SH-H14  SHUNT-HEADER
Z_SH-H15  SHUNT-HEADER
Z_SH-H16  SHUNT-HEADER
sheet SH7 - POWER DISTRIBUTION
C111  1uF  [0603]
C112  .1uF  [0402]
C116  .1uF  [0402]
C117  1uF  [0603]
C118  1uF  [0603]
C133  10uF  [0805]
C134  10uF  [0805]
C135  10uF  [0805]
C145  10uF  [0805]
C146  10uF  [0805]
C147  10uF  [0805]
C148  10uF  [0805]
C149  10uF  [0805]
C152  47uF  [TANT_B]
C153  .1uF  [0402]
C154  1uF  [0402]
C155  10nF  [0402]
C161  10uF  [0805]
C162  10nF  [0402]
C163  2.2uF  [1206]
C164  1uF  [0603]
C165  22uF  [1206]
C166  33pF  [0402]
C167  22uF  [1206]
C169  2.2uF  [0603]
C170  1uF  [0603]
C215  10uF  [0805]
C233  10nF  [0402]
C234  10nF  [0402]
C237  10nF  [0402]
C238  1uF  [0603]
C240  2.2uF  [0603]
C242  10nF  [0402]
C243  10nF  [0402]
C244  1uF  [0603]
C245  10nF  [0402]
C246  1uF  [0603]
C247  10nF  [0402]
D2  Blue  [LED_0805]
F3  2 AMP 63V FAST SMD  [1206]
FB20  68 OHM @ 100MHz  [1206]
FB22  1K  [1810]
FB24  1K  [1810]
FB30  27uF  [1206_BEAD_NFM31P]
FB31  27uF  [1206_BEAD_NFM31P]
FB34  1K  [1810]
FB35  1K  [1810]
J18  CONN JACK PWR  [CON_RAPC722_JACK_THVT_3]
JP10  Jumper_1x3_100_430L  [HDR_THVT_1x3_100_M]
L25  2.2uH  [LPS3015]
L26  2.2uH  [LPS3015]
Q3  CSD17313Q2  [SON_8_2MMX2MM_0P65MM]
R126  0  [0805]
R127  0  [0805]
R128  0  [0805]
R143  10K  [0603]
R145  0  [0805]
R146  0  [0805]
R147  0  [0805]
R148  750K  [0402]
R150  191K  [0402]
R151  150K  [0402]
R153  182K  [0402]
R168  10K  [0402]
R170  30.9K  [0402]
R221  174K  [0402]
R257  174K  [0402]
R315  330K  [0402]
R316  330K  [0402]
TP12  Testloop_Red  [testpoint_62dia]
TP13  Testloop_Black  [testpoint_62dia]
TP15  Testloop_Red  [testpoint_62dia]
TP16  Testloop_Red  [testpoint_62dia]
TP17  Testloop_Red  [testpoint_62dia]
TP18  Testloop_Red  [testpoint_62dia]
TP19  Testloop_Red  [testpoint_62dia]
U11  TPS62420  [SON_DRC_10]
U12  TPS79633  [SOT_223_6_TG]
U13  TPS71701  [SC70_DCK_G5]
U15  TPS7A8001DRB  [SON_8_124x124_pwrpad_DRB]
U21  TPS2400  [DBV5]
U22  TPS71701  [SC70_DCK_G5]
Z_SH-H12  SHUNT-HEADER

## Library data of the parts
C1-C4 = CAP_NP_1: Mfr_Name: Murata; Mfr_Part_Number: GRM155R71E103KA01D; TOL: 10%; VOLTAGE: 25V
C251-C253 C257-C262 C266-C271 C275-C280 C284-C286 = CAP_NP_1: Note: DNI; TOL: .25pF; VOLTAGE: 50V
C254 C256 C264 C265 C273 C274 C282 C283 = CAP_NP_1: Mfr_Name: Murata; Mfr_Part_Number: GJM1555C1H3R3CB01D; Note: DNI; TOL: .25pF; VOLTAGE: 50V
C255 C263 C272 C281 = CAP_NP_1: Mfr_Name: MURATA; Mfr_Part_Number: GJM1555C1H3R3CB01D; Note: DNI; TOL: .25pF; VOLTAGE: 50V
J1 = SMA_PCB_THVT_142-0701-201_REC: Mfr_Name: Johnson Components; Mfr_Part_Number: 142-0701-201; Note: DNI; TI_Silktext: IOUTD1
J2 = SMA_PCB_THVT_142-0701-201_REC: Mfr_Name: Johnson Components; Mfr_Part_Number: 142-0701-201; TI_Silktext: IOUTD2
J3 = SMA_PCB_THVT_142-0701-201_REC: Mfr_Name: Johnson Components; Mfr_Part_Number: 142-0701-201; TI_Silktext: IOUTC2
J4 = SMA_PCB_THVT_142-0701-201_REC: Mfr_Name: Johnson Components; Mfr_Part_Number: 142-0701-201; Note: DNI; TI_Silktext: IOUTC1
J5 = SMA_PCB_THVT_142-0701-201_REC: Mfr_Name: Johnson Components; Mfr_Part_Number: 142-0701-201; Note: DNI; TI_Silktext: IOUTB1
J6 = SMA_PCB_THVT_142-0701-201_REC: Mfr_Name: Johnson Components; Mfr_Part_Number: 142-0701-201; TI_Silktext: IOUTB2
J7 = SMA_PCB_THVT_142-0701-201_REC: Mfr_Name: Johnson Components; Mfr_Part_Number: 142-0701-201; TI_Silktext: IOUTA2
J8 = SMA_PCB_THVT_142-0701-201_REC: Mfr_Name: Johnson Components; Mfr_Part_Number: 142-0701-201; Note: DNI; TI_Silktext: IOUTA1
J20 = SMP_PLUG_SMT: Manufacturer: Molex Inc.; Manufacturer Part Number: 0853050232; Mfr_Name: Molex Inc.; Mfr_Part_Number: 0853050232; TI_Silktext: FIFO_OSTR2_C
J21 = SMP_PLUG_SMT: Manufacturer: Molex Inc.; Manufacturer Part Number: 0853050232; Mfr_Name: Molex Inc.; Mfr_Part_Number: 0853050232; TI_Silktext: FIFO_OSTR2
J22 = SMP_PLUG_SMT: Manufacturer: Molex Inc.; Manufacturer Part Number: 0853050232; Mfr_Name: Molex Inc.; Mfr_Part_Number: 0853050232; TI_Silktext: DACCLK2_C
J23 = SMP_PLUG_SMT: Manufacturer: Molex Inc.; Manufacturer Part Number: 0853050232; Mfr_Name: Molex Inc.; Mfr_Part_Number: 0853050232; TI_Silktext: DACCLK2
L27-L42 = IND0603_0: Mfr_Name: Stackpole Electronics Inc; Mfr_Part_Number: RMCF 1/16S 0 R; TOL: 5%
R4 R13 R16 R20 R24 R25 R28 R32 R34 R36 R40 R42 = R: Mfr_Name: Stackpole Electronics Inc; Mfr_Part_Number: RMCF0402ZT0R00; Note: DNI; TOL: 5%
R5 R15 = RES0603: Mfr_Name: Vishay/Dale; Mfr_Part_Number: CRCW0402100RFKED; TOL: 1%; Wattage: 1/16W
R6 R10 R21 R23 R29 R31 R37 R39 = R: Mfr_Name: Stackpole Electronics Inc; Mfr_Part_Number: RMCF0402FT100R; TOL: 1%
R7 R22 R30 R38 R99-R102 = Res_0603: Mfr_Name: Stackpole Electronics Inc; Mfr_Part_Number: RMCF 1/16S 49.9 1% R; Note: DNI; TOL: 1%
R9 R12 R14 R18 = R: Mfr_Name: Stackpole Electronics Inc; Mfr_Part_Number: RMCF0402ZT0R00; TOL: 5%
R33 R35 R41 R94 R96-R98 R112 = R: Mfr_Name: Stackpole Electronics Inc; Mfr_Part_Number: CRCW020149R9FKED; Note: DNI; TOL: 1%
R104-R111 = R: Mfr_Name: Stackpole Electronics Inc; Mfr_Part_Number: RMCF 1/16S 0 R; TOL: 5%
R95 R122-R125 R129 R130 R133 = R: Mfr_Name: Panasonic; Mfr_Part_Number: ERJ-2GE0R00X; Note: DNI; TOL: 5%
R55 R70 R116 R117 R149 R152 R154-R157 = R: Mfr_Name: Panasonic; Mfr_Part_Number: ERJ-2GE0R00X; TOL: 5%
T1-T4 = ADT4-1T_0: Mfr_Part_Number: ADT4-1WT+
T8-T11 = TFMR_5_ETC1-1-13_4
TP1 TP6-TP9 TP13 = TESTLOOP_BLACK: Mfr_Name: KEYSTONE; Mfr_Part_Number: 5011; TI_SILKTEXT: GND
TP27-TP34 = TEST_POINT_0
U1 = DAC34H84
C5-C10 C12-C19 C21 C25-C29 C31-C33 C38 C41 C43 C45 = CAP_NP_1: Mfr_Name: Taiyo Yuden; Mfr_Part_Number: LMK063BJ224MP-F; TOL: 20%; VOLTAGE: 10V
C11 C20 C23 C39 C42 C44 C46 C49 C51 = CAP0402_0: Mfr_Name: Taiyo Yuden; Mfr_Part_Number: LMK063BJ224MP-F; TOL: 20%; Voltage: 10V
C22 C24 C30 C40 = CAP_POL-B_10uF_10V: Mfr_Name: Kermet; Mfr_Part_Number: T491A106M016AT; Voltage: 10V
C34 C37 C92 C94 C97 C137 C139-C142 C177 C180 C182 = CAP_NP_1: Mfr_Name: Panasonic; Mfr_Part_Number: ECJ-0EB1C104K; TOL: 10%; VOLTAGE: 16V
C35 C47 C50 C53 = CAP_NP_1: Mfr_Name: Panasonic; Mfr_Part_Number: ECJ-0EB1E102K; TOL: 10%; VOLTAGE: 25V
C36 C48 = CAP_NP_1: Mfr_Name: Taiyo Yuden; Mfr_Part_Number: LMK063BJ104KP-F; TOL: 10%; VOLTAGE: 10V
FB1 = FERRITE_BEAD: DCR: .500 Ohm; Mfr_Name: Murata; Mfr_Part_Number: BLM18HE152SN1D
JP2 JP10 = Jumper_1x3_100_0: Mfr_Name: SAMTEC; Mfr_Part_Number: HMTSW-103-07-G-S-.230; Note: (SHUNT 1-2); TI_Silktext: TXENABLE
JP3 = Jumper_1x3_100_0: Mfr_Name: SAMTEC; Mfr_Part_Number: HMTSW-103-07-G-S-.230; Note: (SHUNT 2-3); TI_Silktext: SLEEP
R43 = R_0: Mfr_Name: Panasonic; Mfr_Part_Number: ERJ-2RKF1001X; TOL: 1%
R44 = R_0: Mfr_Name: Panasonic; Mfr_Part_Number: ERJ-2RKF1271X; TOL: 1%
R45 = R_0: Mfr_Name: Vishay/Dale; Mfr_Part_Number: CRCW040210R0FKED; TOL: 1%
R46 = R_0: Mfr_Name: Panasonic; Mfr_Part_Number: ERJ-2RKF1001X; PART_NUMBER: Panasonic ERJ-2RKF1001X; TOL: 1%
SW1 SW2 = SPST_PB_KT11P3JM_5: Mfr_Name: C&K; Mfr_Part_Number: KT11P3JM; TI_SILKTEXT: RESET
TP2 = TESTLOOP_BLACK: Mfr_Name: KEYSTONE; Mfr_Part_Number: 5012; TI_SILKTEXT: EXTIO
TP3 = TESTLOOP_BLACK: Mfr_Name: Components Corporation; Mfr_Part_Number: TP-105-01-00; TI_SILKTEXT: GND
TP4 = TESTLOOP_BLACK: Mfr_Name: KEYSTONE; Mfr_Part_Number: 5012; TI_SILKTEXT: TESTMODE
TP5 = TESTLOOP_BLACK: Mfr_Name: KEYSTONE; Mfr_Part_Number: 5012; TI_SILKTEXT: ALARMB
TP25 TP26 = TESTLOOP_BLACK: Mfr_Name: KEYSTONE; Mfr_Part_Number: 5012; TI_SILKTEXT: LPF
Z_SH-H2 Z_SH-H3 Z_SH-H6 Z_SH-H7 Z_SH-H12 = SHUNT-HEADER
C52 C59-C62 C66 C68 C71 C72 C74 C79-C81 C83 C85 C87 C89 C104 C128 = CAP_NP_1: Mfr_Name: TDK; Mfr_Part_Number: C1608X5R1A475K; TOL: 10%; VOLTAGE: 10V
C55 = CAP_NP_1: Mfr_Name: Kemet; Mfr_Part_Number: C0603C274K8PACTU; TOL: 10%; VOLTAGE: 10V
C56-C58 C65 C67 C69 C70 C73 C76-C78 C82 C84 C86 C88 C127 = CAP_NP_1: Mfr_Name: Panasonic; Mfr_Part_Number: ECJ-ZEB1A103K; TOL: 10%; VOLTAGE: 10V
C63 = CAP_NP_1: Mfr_Name: Murata; Mfr_Part_Number: GRM155R61A105KE15D; TOL: 10%; VOLTAGE: 10V
C64 C75 = CAP_NP_1: Mfr_Name: Murata; Mfr_Part_Number: GRM21BR61A106KE19L; TOL: 10%; VOLTAGE: 10V
C178 = CAP_NP_1: Mfr_Name: Panasonic; Mfr_Part_Number: ECJ-0EB1E101K; PART_NUMBER: Panasonic ECJ-0EB1E101K; TOL: 10%; VOLTAGE: 25V
C179 = CAP_NP_1: Mfr_Name: Taiyo Yuden; Mfr_Part_Number: AMK105BJ475MV-F; TOL: 20%; VOLTAGE: 4V
C181 = CAP_POL-B_10uF_10V: Mfr_Name: Kermet; Mfr_Part_Number: T494A106M016AT; Tol: 20%; Voltage: 16V
D1 = LED: Mfr_Name: Panasonic; Mfr_Part_Number: LNJ306G5PRX; PART_NUMBER: Panasonic LNJ306G5UUX; TI_Silktext: LOCK
FB3 FB5 FB8-FB13 FB15 = FERRITE_BEAD: DCR: 90 mOhm; Mfr_Name: Murata; Mfr_Part_Number: BLM15PD121SN1D
FB4 FB6 FB7 FB25 = FERRITE_BEAD: DCR: 490 mOhm; Mfr_Name: Murata; Mfr_Part_Number: BLM15AX102SN1D
J9 = SMA-END_JACK_142-0761-801_ROUND: TI_Silktext: EXT_REF_CLK
J10 = SMP_PLUG_SMT: Manufacturer: Molex Inc.; Manufacturer Part Number: 0853050232; Mfr_Name: Molex Inc.; Mfr_Part_Number: 0853050232; TI_Silktext: CDC-IO2
J11 = SMP_PLUG_SMT: Manufacturer: Molex Inc.; Manufacturer Part Number: 0853050232; Mfr_Name: Molex Inc.; Mfr_Part_Number: 0853050232; TI_Silktext: CDC-IO2\
J12 = SMP_PLUG_SMT: Manufacturer: Molex Inc.; Manufacturer Part Number: 0853050232; Mfr_Name: Molex Inc.; Mfr_Part_Number: 0853050232; TI_Silktext: CDC_IO1
J15 = SMP_PLUG_SMT: Manufacturer: Molex Inc.; Manufacturer Part Number: 0853050232; Mfr_Name: Molex Inc.; Mfr_Part_Number: 0853050232; TI_Silktext: CDC_IO1\
J19 = SMP_PLUG_SMT: Manufacturer: Molex Inc.; Manufacturer Part Number: 0853050232; Mfr_Name: Molex Inc.; Mfr_Part_Number: 0853050232; TI_Silktext: SYNC
JP4 = Jumper_1x3_100_0: Mfr_Name: SAMTEC; Mfr_Part_Number: HMTSW-103-07-G-S-.230; Note: (SHUNT 2-3); TI_Silktext: PRIREF-
JP5 = Jumper_1x3_100_0: Mfr_Name: SAMTEC; Mfr_Part_Number: HMTSW-103-07-G-S-.230; Note: (SHUNT 1-2); TI_Silktext: REFSEL
JP6 = Jumper_1x3_100_0: Mfr_Name: SAMTEC; Mfr_Part_Number: HMTSW-103-07-G-S-.230; Note: (SHUNT 1-2); TI_Silktext: CDC_PD
JP7-JP9 JP12 JP13 = JUMPER_1x2_100: Note: SHORTED
R47 R51 = R: Mfr_Name: Panasonic; Mfr_Part_Number: ERJ-2RKF82R5X; TOL: 1%
R48 = R: Mfr_Name: Panasonic; Mfr_Part_Number: ERJ-2RKF1101X; TOL: 1%
R49 = R: Mfr_Name: Panasonic; Mfr_Part_Number: ERJ-2RKF49R9X_DNI; Note: DNI; TOL: 1%
R50 R103 = R: Mfr_Name: Panasonic; Mfr_Part_Number: ERJ-2RKF1300X; TOL: 1%
R52 = R: Mfr_Name: Vishay; Mfr_Part_Number: CRCW0402301RFKED; TOL: 1%
R53 R57 = R: Mfr_Name: PANASONIC; Mfr_Part_Number: ERJ-2RKF1300X; Note: DNI; TOL: 1%
R54 R58 = R_0: Mfr_Name: PANASONIC; Mfr_Part_Number: ERJ-2GE0R00X; PART_NUMBER: Panasonic ERJ-2RKF22R1X; TOL: 1%
R56 = R: Mfr_Name: PANASONIC; Mfr_Part_Number: ERJ-2RKF82R5X; Note: DNI; TOL: 1%
R59 = R: Mfr_Name: Panasonic; Mfr_Part_Number: ERJ-2RKF82R5X; Note: DNI; TOL: 1%
R60 R61 = R: Mfr_Name: Panasonic; Mfr_Part_Number: ERJ-2RKF1300X; PART_NUMBER: Panasonic ERJ-2RKF1300X; TOL: 1%
R62 R63 R68 R69 R89 R91 = R: Mfr_Name: Panasonic; Mfr_Part_Number: ERJ-2RKF1300X; Note: DNI; PART_NUMBER: Panasonic ERJ-2RKF1300X; TOL: 1%
R64 R65 = R: Mfr_Name: Panasonic; Mfr_Part_Number: ERJ-2RKF82R5X; PART_NUMBER: Panasonic ERJ-2RKF82R5X; TOL: 1%
R66 R67 R71 R72 R90 R92 = R: Mfr_Name: Panasonic; Mfr_Part_Number: ERJ-2RKF1500X; TOL: 1%
R88 = R: Mfr_Name: PANASONIC; Mfr_Part_Number: ERJ-2GE0R00X; TOL: 5%
R93 = R: Mfr_Name: PANASONIC; Mfr_Part_Number: 0853050232; TOL: 5%
R120 R121 = R: Mfr_Name: PANASONIC; Mfr_Part_Number: ERJ-2GE0R00X; Note: DNI; TOL: 5%
R164 R165 = R: Mfr_Name: Panasonic; Mfr_Part_Number: ERJ-2RKF1002X; Note: DNI; PART_NUMBER: Panasonic ERJ-2RKF1002X; TOL: 1%
R74 R83 R166 R167 = R: Mfr_Name: Panasonic; Mfr_Part_Number: ERJ-2RKF1002X; PART_NUMBER: Panasonic ERJ-2RKF1002X; TOL: 1%
TP14 = TESTLOOP_BLACK: Mfr_Name: KEYSTONE; Mfr_Part_Number: 5012; TI_SILKTEXT: REF_ADJ
U2 = ARES_0: Manufacturer: TI; Mfr_Name: Texas Instruments; Mfr_Part_Number: CDCE62005RGZT; Note: TI Supplied
U16 = OSC-VECTRON_2: Mfr_Name: Connor-Winfield; Mfr_Part_Number: D75A-019.2 MHZ; Note: DNI
U17 = OSC-VECTRON_0: Mfr_Name: Vectron; Mfr_Part_Number: VTD3-J0BC-19M200; TI Supplied: YES
Z_SH-H4 = SHUNT-HEADER: Mfr_Name: Keltron; Mfr_Part_Number: MJ-5.97-G
Z_SH-H5 Z_SH-H13-Z_SH-H16 = SHUNT-2PINHEADER
C54 = CAP_NP: CLASS: DISCRETE; Mfr_Name: Panasonic; Mfr_Part_Number: ECJ-0EB1E103K; TOL: 10%; VOLTAGE: 25V
C90 C99-C103 = CAP_NP_1: Mfr_Name: Panasonic; Mfr_Part_Number: ECJ-0EB1E103K; TOL: 10%; VOLTAGE: 25V
R131 = R: Mfr_Name: Panasonic; Mfr_Part_Number: ERJ-2RKF6042X; TOL: 1%
R206 R207 = RESISTOR: CLASS: DISCRETE; Mfr_Name: Panasonic; Mfr_Part_Number: ERJ-2RKF49R9X; TOL: 1%
U6 = CDCM1804_MLF24_3: CLASS: IC; Mfr_Name: Texas Instruments; Mfr_Part_Number: CDCM1803RGET; PART_NUMBER: CDCM1803RGET
C133 C134 C143-C149 = CAP_NP: CLASS: DISCRETE; Mfr_Name: Murata; Mfr_Part_Number: GRM21BR71A106KE51L; Part Number: ECJ-3YB1C106K; TOL: 10%; VOLTAGE: 10V
J13 = CON_SMVT_180POS_QTH_SAMTEC: Mfr_Part_Number: QTH-090-01-L-D-A-RT1
SJP9-SJP12 = Jumper_1x3_100_0: Manufacturer: NO PART; Mfr_Name: NO PART; Note: (SHUNT 1-2)
Z_BOARD1 = BARE_BOARD: Mfr_Part_Number: DAC34H84_34SH84_REV_D
Z_SCREW1-Z_SCREW4 = STANDOFF-SCREW
Z_SH-H8-Z_SH-H11 = SHUNT-HEADER: Manufacturer: NO PART; Mfr_Name: Stackpole Electronics Inc; Mfr_Part_Number: RMCF0402ZT0R00
Z_STANDOFF1-Z_STANDOFF4 = STANDOFF: Mfr_Part_Number: 2204
C91 = CAP0603: Mfr_Name: Murata; Mfr_Part_Number: GRM155R71E103KA01D; TOL: 10%; VOLTAGE: 25V
C93 = CAP_POL-B_10uF_10V: Mfr_Name: AVX; Mfr_Part_Number: TAJA475K020R; PART_NUMBER: AVX TAJA475K020R; TOL: 10%; VOLTAGE: 20V
C95 C96 = CAP0603: Mfr_Name: Murata; Mfr_Part_Number: GRM1555C1H470JZ01D; TOL: 5%; VOLTAGE: 50V
C98 = CAP_NP_1: Mfr_Name: Panasonic; Mfr_Part_Number: ECJ-0EB1C104K; PART_NUMBER: Panasonic  ECJ-0EB1C104K; TOL: 10%; VOLTAGE: 16V
C136 = CAP_NP_2: Mfr_Name: TDK; Mfr_Part_Number: C1005X5R1C105K; TOL: 10%; VOLTAGE: 16V
C138 = CAP0603: Mfr_Name: Johanson Technology Inc; Mfr_Part_Number: 500R07S150GV4T; TOL: 2%; VOLTAGE: 50V
C250 = CAP_NP_1: Mfr_Name: Murata; Mfr_Part_Number: GRM188R61A225KE34D; TOL: 10%; VOLTAGE: 10V
FB14 = FERRITE_BEAD: Mfr_Name: Panasonic; Mfr_Part_Number: EXC-ML32A680U; PART_NUMBER: Panasonic EXC-ML32A680U
J14 = USB_MINI_AB_MNE20-5G5P10: Mfr_Name: JAE; Mfr_Part_Number: DX3R005HN2E700; TI_SILKTEXT: USB
JP11 = JUMPER_3X2_SMT_0: Mfr_Name: FCI; Mfr_Part_Number: 67996-104HLF; Note: (NO SHUNT)
R73 = R: Mfr_Name: Panasonic; Mfr_Part_Number: ERJ-2RKF1002X; TOL: 1%
R75-R82 = R_0: Mfr_Name: Panasonic; Mfr_Part_Number: ERJ-2RKF22R1X; PART_NUMBER: Panasonic ERJ-2RKF22R1X; TOL: 1%
R84 = R: Mfr_Name: Panasonic; Mfr_Part_Number: ERJ-2RKF1000X; TOL: 1%
R85-R87 R138-R140 = R: Mfr_Name: Panasonic; Mfr_Part_Number: ERJ-2RKF1000X; PART_NUMBER: Panasonic ERJ-2RKF1000X; TOL: 1%
R134 = R: Mfr_Name: Yageo; Mfr_Part_Number: RC0402FR-0730K1L; TOL: 1%
R135 = R: Mfr_Name: Panasonic; Mfr_Part_Number: ERJ-2RKF5112X; TOL: 1%
R136 = R: Mfr_Name: Panasonic; Mfr_Part_Number: ERJ-2RKF1962X; TOL: 1%
R137 = R: Mfr_Name: Panasonic; Mfr_Part_Number: ERJ-2RKF8202X; TOL: 1%
U3 = FT245RL_0: Mfr_Name: FTDI Chip
U4 U5 = 74AVC2T245: Mfr_Name: Texas Instruments; Mfr_Part_Number: SN74AVC2T245RSWR
U9 = 74LVC125A: Mfr_Name: Texas Instruments; Mfr_Part_Number: SN74LVC125APWRG3
U10 = 74LVC1G126: Mfr_Name: Texas Instruments; Mfr_Part_Number: 74LVC1G126DBVRE4
U20 = TPS79633DCQ_1: Manufacturer: TI; Mfr_Part_Number: TPS79601DCQ; PART_NUMBER: TPS79601DCQ
C111 C117 C118 = CAP_NP_2: Mfr_Name: Panasonic; Mfr_Part_Number: ECJ-1V41E105M; TOL: 20%; VOLTAGE: 25V
C112 C116 = CAP_NP: Mfr_Name: Panasonic; Mfr_Part_Number: ECJ-0EB1C104K; PART_NUMBER: Panasonic  ECJ-0EB1C104K; Part Number: ECJ-0EB1C104K; TOL: 10%; VOLTAGE: 16V
C135 C215 = CAP0201: Mfr_Name: Murata; Mfr_Part_Number: GRM21BR71A106KE51L; TOL: 20%; VOLTAGE: 10V
C152 = CAP_POL: Mfr_Name: KEMET; Mfr_Part_Number: T494B476M010AT; TOL: 10%; VOLTAGE: 10V
C153 = CAP_NP: Mfr_Name: MURATA; Mfr_Part_Number: GRM155R61C104KA88D; TOL: 10%
C154 = CAP_NP_1: Mfr_Name: TDK; Mfr_Part_Number: C1005X5R1C105K; TOL: 10%; VOLTAGE: 16V
C155 = CAP_NP_1: Mfr_Name: TDK; Mfr_Part_Number: C1005X7R1E103K; TOL: 10%; VOLTAGE: 25V
C161 = CAP_NP: CLASS: DISCRETE; Mfr_Name: Murata; Mfr_Part_Number: GRM21BR71A106KE51L; PART_NUMBER: Panasonic ECJ-3YB1C106K; Part Number: ECJ-3YB1C106K; TOL: 10%; VOLTAGE: 10V
C162 C243 = CAPACITOR_NP_4: CAP, CERAMIC, 0.01uF, 0402, 10%, 25VDC, X7R; Manufacturer: Kemet; Mfr_Name: Panasonic; Mfr_Part_Number: C0402C103K3RACTU; PART_NUMBER: C0402C103K3RACTU; TOL: 10%; VOLTAGE: 25V
C163 = CAP_POL-B: Manufacturer: Panasonic; Mfr_Name: Panasonic; Mfr_Part_Number: ECJ-HVB1A225K; PART_NUMBER: ECJ-HVB1A225K; TOL: 10%; VOLTAGE: 10V
C164 C170 C238 C244 C246 = CAP_NP_1: Mfr_Name: Panasonic; Mfr_Part_Number: ECJ-1V41E105M; TOL: 20%; VOLTAGE: 25V
C165 C167 = CAP_NP_1: Mfr_Name: Murata; Mfr_Part_Number: GRM31CR60J226KE19L; TOL: 10%; VOLTAGE: 6.3V
C166 = CAP_NP_1: Mfr_Name: Johansen Technology; Mfr_Part_Number: 250R07S330GV4T; TOL: 2%; VOLTAGE: 25V
C169 C240 = CAP_NP_1: Mfr_Name: Panasonic; Mfr_Part_Number: ECJ-1VB1A225K; TOL: 10%; VOLTAGE: 10V
C233 C234 C237 C242 C245 C247 = CAPACITOR_NP_4: CAP, CERAMIC, 0.01uF, 0402, 10%, 25VDC, X7R; Mfr_Name: TDK; Mfr_Part_Number: C1005X7R1E103K; TOL: 10%; VOLTAGE: 25V
D2 = LED: Mfr_Name: Lite On; Mfr_Part_Number: LTST-C170TBKT; TI_Silktext: +6V
F3 = FUSE_SM: Mfr_Part_Number: 1206SFF200F/63-2_DNI; Note: DNI
FB20 = FERRITE_BEAD: Mfr_Name: Panasonic; Mfr_Part_Number: EXC-ML32A680U
FB22 FB24 FB34 FB35 = FERRITE_BEAD_0402_H: Mfr_Name: Taiyo Yuden; Mfr_Part_Number: FBMH4525HM102NT
FB30 FB31 = BEAD_NFM31P: Mfr_Name: MURATA; Mfr_Part_Number: NFM31PC276B0J3; Tolerance: 20%
J18 = CONN_JACK_PWR: Mfr_Name: Switchcraft; Mfr_Part_Number: RAPC722; PART_NUMBER: Switchcraft RAPC722; Part Number: RAPC722
L25 L26 = IND1206: Mfr_Name: Coilcraft; Mfr_Part_Number: LPS3015-222ML; Tolerance: 20%
Q3 = PWR_MOSFET_CSD17313Q2: Mfr_Name: Texas Instruments
R126 R127 = RES0603: Mfr_Name: Stackpole Electronics Inc; Mfr_Part_Number: RMCF0805ZT0R00; Note: DNI; TOL: 5%; Wattage: 1/8W
R128 = RES0603: Mfr_Name: Stackpole Electronics Inc; Mfr_Part_Number: RMCF0805ZT0R00; TOL: 5%; Wattage: 1/8W
R143 = RES0603: Mfr_Name: Panasonic; Mfr_Part_Number: ERJ-3EKF1002V; TOL: 1%; Wattage: 1/10W
R145 = R: Mfr_Name: Stackpole Electronics Inc; Mfr_Part_Number: RMCF0805ZT0R00; Note: DNI; TOL: 5%; Wattage: 1/8W
R146 R147 = R: Mfr_Name: Stackpole Electronics Inc; Mfr_Part_Number: RMCF0805ZT0R00; TOL: 5%; Wattage: 1/8W
R148 = R: CLASS: DISCRETE; Mfr_Name: Vishay/Dale; Mfr_Part_Number: CRCW0402750KJNED; TOL: 1%; Wattage: 1/16W
R150 = R: CLASS: DISCRETE; Mfr_Name: Vishay/Dale; Mfr_Part_Number: CRCW0402191KFKED; TOL: 1%; Wattage: 1/16W
R151 = R: CLASS: DISCRETE; Mfr_Name: Yageo; Mfr_Part_Number: RC0402FR-07150KL; TOL: 1%; Wattage: 1/16W
R153 = R: CLASS: DISCRETE; Mfr_Name: Vishay/Dale; Mfr_Part_Number: CRCW0402182KFKED; TOL: 1%; Wattage: 1/16W
R168 = R: CLASS: DISCRETE; Mfr_Name: Panasonic; Mfr_Part_Number: ERJ-2GEJ103X; TOL: 1%; Wattage: 1/16W
R170 = R: CLASS: DISCRETE; Mfr_Name: Stackpole Electronics Inc; Mfr_Part_Number: RMCF0402FT30K9; TOL: 1%; Wattage: 1/16W
R221 R257 = R: Mfr_Name: Panasonic; Mfr_Part_Number: ERJ-2RKF1743X; TOL: 1%
R315 R316 = R: Mfr_Name: Panasonic; Mfr_Part_Number: ERJ-2RKF3303X; TOL: 1%
TP12 = TESTLOOP_BLACK: Mfr_Name: Keystone; Mfr_Part_Number: 5010; TI_SILKTEXT: VCC_IN
TP15 = TESTLOOP_BLACK: Mfr_Name: Keystone; Mfr_Part_Number: 5005; TI_SILKTEXT: +1.2VD
TP16 = TESTLOOP_BLACK: Mfr_Name: Keystone; Mfr_Part_Number: 5005; TI_SILKTEXT: +3.3VA
TP17 = TESTLOOP_BLACK: Mfr_Name: Keystone; Mfr_Part_Number: 5005; TI_SILKTEXT: +3.3VCLK
TP18 = TESTLOOP_BLACK: Mfr_Name: Keystone; Mfr_Part_Number: 5005; TI_SILKTEXT: +1.2VDAC
TP19 = TESTLOOP_BLACK: Mfr_Name: Keystone; Mfr_Part_Number: 5005; TI_SILKTEXT: +1.2VCLK
U11 = TPS62420_SON10_1: Mfr_Name: Texas Instruments; Mfr_Part_Number: TPS62420DRCR
U12 = TPS79633DCQ_1: Manufacturer: TI; PART_NUMBER: TPS79633DCQ
U13 U22 = TPS79633DCQ_2: Manufacturer: TI; Mfr_Part_Number: TPS71701DCKR
U15 = TPS7A8001DRB
U21 = TPS2400: Mfr_Name: Texas Instruments; Mfr_Part_Number: TPS2400DBVT

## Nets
+1.2VCLK: C38.1 C39.1 C40.1 C148.1 C238.1 C242.1 FB35.2 TP19.1(TP) U1.C12(CLKVDD) U1.K12(CLKVDD)
+1.2VD: C25.1 C26.1 C27.1 C28.1 C29.1 C30.1 C31.1 C32.1 C33.1 C36.1 C134.1 C233.1 FB30.3 TP15.1(TP) U1.D7(VFUSE1) U1.E5(DIGVDD) U1.E6(DIGVDD) U1.E7(DIGVDD) U1.F5(DIGVDD) U1.J5(DIGVDD) U1.K5(DIGVDD) U1.K6(DIGVDD) U1.K7(DIGVDD) U1.L7(VFUSE2)
+1.2VDAC: C13.1 C14.1 C15.1 C16.1 C17.1 C18.1 C19.1 C20.1 C21.1 C23.1 C24.1 C147.1 C170.1 C243.1 FB34.2 TP18.1(TP) U1.D9(DACDVDD) U1.E9(DACDVDD) U1.E10(DACDVDD) U1.F10(DACDVDD) U1.G10(DACDVDD) U1.H10(DACDVDD) U1.J10(DACDVDD) U1.K9(DACDVDD) U1.K10(DACDVDD) U1.L9(DACDVDD)
+3.3V_LOGIC: C139.1 C141.1 FB24.2 U4.6(VCCB) U5.6(VCCB)
+3.3VA: C5.1 C6.1 C7.1 C8.1 C9.1 C10.1 C11.1 C12.1 C22.1 FB1.2 FB22.1 R145.1 R147.2 TP16.1(TP) U1.D10(AVDD33) U1.E11(AVDD33) U1.F11(AVDD33) U1.G11(AVDD33) U1.H11(AVDD33) U1.J11(AVDD33) U1.K11(AVDD33) U1.L10(AVDD33)
+3.3VCLK: C102.1 C103.1 C104.1 C118.1 C127.1 C128.1 C179.1 C215.1 FB3.1 FB4.1 FB5.1 FB6.1 FB7.1 FB8.1 FB9.1 FB10.1 FB11.1 FB12.1 FB13.2 FB15.2 FB24.1 JP5.1(Pin1) JP6.1(Pin1) JP7.2 R47.1 R51.1 R53.1 R57.1 R60.1 R61.1 R62.1 R63.1 R68.1 R69.1 R89.1 R91.1 R166.1 R170.2 TP17.1(TP) U2.15(VCC_AUXOUT) U6.1(EN) U6.2(VDDPECL) U6.5(VDDPECL) U15.1(OUT1) U15.2(OUT2)
+3.3VD: C41.1 C42.1 C43.1 C44.1 C45.1 C46.1 FB22.2 U1.D5(IOVDD) U1.D6(IOVDD) U1.G5(IOVDD) U1.H5(IOVDD) U1.L5(IOVDD) U1.L6(IOVDD)
+5V_USB: C91.1 C136.1 C137.1 FB14.2 J14.1(VBUS) U20.1(EN) U20.2(IN)
GNDA: C5.2 C6.2 C7.2 C8.2 C9.2 C10.2 C11.2 C12.2 C13.2 C14.2 C15.2 C16.2 C17.2 C18.2 C19.2 C20.2 C21.2 C22.2 C23.2 C24.2 C25.2 C26.2 C27.2 C28.2 C29.2 C30.2 C31.2 C32.2 C33.2 C34.2 C35.2 C36.2 C37.2 C38.2 C39.2 C40.2 C41.2 C42.2 C43.2 C44.2 C45.2 C46.2 C47.2 C48.2 C49.2 C50.2 C51.2 C54.1 C56.2 C57.2 C58.2 C59.2 C60.2 C61.2 C62.2 C63.1 C64.1 C65.2 C66.2 C67.2 C68.2 C69.2 C70.2 C71.2 C72.2 C73.2 C74.2 C75.1 C76.2 C77.2 C78.2 C79.2 C80.2 C81.2 C82.2 C83.2 C84.2 C85.2 C86.2 C87.2 C88.2 C89.2 C90.2 C91.2 C92.2 C93.2 C94.2 C95.2 C96.2 C97.2 C98.2 C101.2 C102.2 C103.2 C104.2 C111.2 C112.2 C116.2 C117.2 C118.2 C127.2 C128.2 C133.2 C134.2 C135.2 C136.2 C137.2 C139.2 C140.2 C141.2 C142.2 C143.2 C144.2 C145.2 C146.2 C147.2 C148.2 C149.2 C152.2 C153.2 C154.2 C155.2 C161.2 C162.2 C163.2 C164.2 C165.2 C167.2 C169.2 C170.2 C178.2 C179.2 C180.2 C181.2 C182.2 C215.2 C233.2 C234.2 C237.2 C238.2 C240.2 C242.2 C243.2 C244.2 C245.2 C246.2 C247.2 C250.2 C251.1 C252.1 C253.1 C257.2 C258.2 C259.2 C260.1 C261.1 C262.1 C266.2 C267.2 C268.2 C269.1 C270.1 C271.1 C275.2 C276.2 C277.2 C278.1 C279.1 C280.1 C284.2 C285.2 C286.2 D1.2(CATHODE) D2.2(CATHODE) FB30.2 FB31.2 J1.2(SHIELD1) J1.3(SHIELD2) J1.4(SHIELD3) J1.5(SHIELD4) J2.2(SHIELD1) J2.3(SHIELD2) J2.4(SHIELD3) J2.5(SHIELD4) J3.2(SHIELD1) J3.3(SHIELD2) J3.4(SHIELD3) J3.5(SHIELD4) J4.2(SHIELD1) J4.3(SHIELD2) J4.4(SHIELD3) J4.5(SHIELD4) J5.2(SHIELD1) J5.3(SHIELD2) J5.4(SHIELD3) J5.5(SHIELD4) J6.2(SHIELD1) J6.3(SHIELD2) J6.4(SHIELD3) J6.5(SHIELD4) J7.2(SHIELD1) J7.3(SHIELD2) J7.4(SHIELD3) J7.5(SHIELD4) J8.2(SHIELD1) J8.3(SHIELD2) J8.4(SHIELD3) J8.5(SHIELD4) J9.2(GND) J9.3(GND) J9.4(GND) J9.5(GND) J10.2(SHIELD1) J11.2(SHIELD1) J12.2(SHIELD1) J13.29 J13.35 J13.65 J13.66 J13.71 J13.72 J13.77 J13.78 J13.83 J13.84 J13.89 J13.90 J13.95 J13.96 J13.101 J13.102 J13.107 J13.108 J13.113 J13.114 J13.119 J13.120 J13.125 J13.126 J13.131 J13.132 J13.137 J13.138 J13.143 J13.144 J13.149 J13.150 J13.155 J13.156 J13.161 J13.162 J13.167 J13.168 J13.173 J13.174 J13.179 J13.180 J13.181(GND) J13.182(GND) J13.183(GND) J13.184(GND) J13.185(GND) J13.186(GND) J13.187(GND) J13.188(GND) J13.189(GND) J13.190(GND) J13.191(GND) J13.192(GND) J14.5(GND) J14.6(GND1) J14.7(GND2) J14.8(GND3) J14.9(GND4) J15.2(SHIELD1) J18.2 J18.3 J19.2(SHIELD1) J20.2(SHIELD1) J21.2(SHIELD1) J22.2(SHIELD1) J23.2(SHIELD1) JP2.3(Pin3) JP3.3(Pin3) JP4.1(Pin1) JP5.3(Pin3) JP6.3(Pin3) R6.1 R9.2 R10.2 R12.2 R14.2 R18.2 R21.1 R23.2 R29.1 R31.2 R33.2 R35.2 R37.1 R39.2 R41.2 R45.2 R49.1 R50.2 R55.1 R56.2 R59.2 R64.2 R65.2 R66.2 R67.2 R71.2 R72.2 R90.2 R92.2 R94.2 R96.2 R97.2 R98.2 R103.1 R112.2 R131.2 R134.2 R151.1 R153.1 R164.1 R167.1 R168.1 R315.1 R316.1 SW1.1 SW1.2 SW2.1 SW2.2 T1.1(primary) T2.3(primary_dot) T3.1(primary) T4.3(primary_dot) TP1.1(TP) TP3.1(TP) TP6.1(TP) TP7.1(TP) TP8.1(TP) TP9.1(TP) TP13.1(TP) TP27.1 TP28.1 TP29.1 TP30.1 TP31.1 TP32.1 TP33.1 TP34.1 U1.A10(GND) U1.A13(GND) U1.A14(GND) U1.B10(GND) U1.B11(GND) U1.B12(GND) U1.B13(GND) U1.C5(GND) U1.C6(GND) U1.C7(GND) U1.C8(GND) U1.C9(GND) U1.C10(GND) U1.C13(GND) U1.D8(GND) U1.D13(GND) U1.D14(GND) U1.E8(GND) U1.E12(GND) U1.E13(GND) U1.F6(GND) U1.F7(GND) U1.F8(GND) U1.F9(GND) U1.F12(GND) U1.F13(GND) U1.G6(GND) U1.G7(GND) U1.G8(GND) U1.G9(GND) U1.G13(GND) U1.G14(GND) U1.H6(GND) U1.H7(GND) U1.H8(GND) U1.H9(GND) U1.H13(GND) U1.H14(GND) U1.J6(GND) U1.J7(GND) U1.J8(GND) U1.J9(GND) U1.J12(GND) U1.J13(GND) U1.K8(GND) U1.K13(GND) U1.L8(GND) U1.L13(GND) U1.L14(GND) U1.M5(GND) U1.M6(GND) U1.M7(GND) U1.M8(GND) U1.M9(GND) U1.M10(GND) U1.M11(GND) U1.M12(GND) U1.M13(GND) U1.N13(GND) U1.P13(GND) U1.P14(GND) U2.2(SEC_REF-) U2.36(GND_VCO) U2.43(AUX_IN) U2.49(GND_PAD) U3.7(GND) U3.18(GND) U3.21(GND) U3.25(AGND) U3.26(TEST) U4.2(~{OE}) U4.3(GND) U5.1(DIR2) U5.2(~{OE}) U5.3(GND) U6.7(VSS) U6.8(VDD2) U6.11(VDD2) U6.13(VSS) U6.18(S0) U6.20(VDD0) U6.23(VDD0) U6.24(S2) U6.25(PWRPAD) U9.1(1~{OE}) U9.4(2~{OE}) U9.7(GND) U9.10(3~{OE}) U10.3(GND) U11.8(GND) U11.11(THERMPAD) U12.3(GND) U12.6(GND) U13.2(GND) U15.4(GND) U15.9(PWRPAD) U16.4(GND) U17.4(GND) U20.3(GND) U20.6(GND) U21.2(GND) U22.2(GND)
VCC: C111.1 C112.1 C117.1 C135.1 C154.1 C155.1 C161.1 C237.1 FB20.1 R143.2 U11.2(MODE/DATA) U11.3(VIN) U11.7(EN1) U11.9(EN2) U15.5(EN) U15.7(IN2) U15.8(IN1)
VCC_AUXIN: C58.1 C61.1 FB3.2 U2.44(VCC_AUXIN)
VCC_PLL: C56.1 C57.1 C59.1 C60.1 FB4.2 U2.39(VCC2_PLL) U2.42(VCC2_PLL)
VCC_VCO: C69.1 C70.1 C71.1 C72.1 FB7.2 U2.34(VCC_VCO) U2.35(VCC_VCO)
VDD1: C62.1 C90.1 C101.1 FB15.1 U6.14(VDD1) U6.17(VDD1)
A1OUT: J8.1(CENTER) R42.2
A2OUT: J7.1(CENTER) R40.2 T4.1(primary)
ALARM: TP5.1(TP) U1.N12(ALARM)
B1OUT: J5.1(CENTER) R28.2
B2OUT: J6.1(CENTER) R32.1 T3.3(primary_dot)
C1OUT: J4.1(CENTER) R25.2
C2OUT: J3.1(CENTER) R24.2 T2.1(primary)
CDC-PRIREF+: C53.2 R47.2 R50.1 U2.45(PRI_REF+)
CDC-PRIREF-: JP4.2(Pin2) U2.46(PRI_REF-)
CDC_READ: R78.2 U3.11(D3)
CDCOUT: R53.2 R54.1 R56.1 R88.2 R121.2
CDCOUT\: R57.2 R58.1 R59.1 R93.2 R120.2
D1OUT: J1.1(CENTER) R4.2
D2OUT: J2.1(CENTER) R13.1 T1.3(primary_dot)
DA0N: J13.165 U1.G3(DA0N)
DA0P: J13.163 U1.G4(DA0P)
DA1N: J13.159 U1.F1(DA1N)
DA1P: J13.157 U1.F2(DA1P)
DA2N: J13.153 U1.F3(DA2N)
DA2P: J13.151 U1.F4(DA2P)
DA3N: J13.147 U1.E1(DA3N)
DA3P: J13.145 U1.E2(DA3P)
DA4N: J13.141 U1.E3(DA4N)
DA4P: J13.139 U1.E4(DA4P)
DA5N: J13.135 U1.D1(DA5N)
DA5P: J13.133 U1.D2(DA5P)
DA6N: J13.129 U1.D3(DA6N)
DA6P: J13.127 U1.D4(DA6P)
DA7N: J13.123 U1.C1(DA7N)
DA7P: J13.121 U1.C2(DA7P)
DA8N: J13.111 U1.C3(DA8N)
DA8P: J13.109 U1.C4(DA8P)
DA9N: J13.105 U1.B1(DA9N)
DA9P: J13.103 U1.A1(DA9P)
DA10N: J13.99 U1.B2(DA10N)
DA10P: J13.97 U1.A2(DA10P)
DA11N: J13.93 U1.B3(DA11N)
DA11P: J13.91 U1.A3(DA11P)
DA12N: J13.87 U1.B4(DA12N)
DA12P: J13.85 U1.A4(DA12P)
DA13N: J13.81 U1.B5(DA13N)
DA13P: J13.79 U1.A5(DA13P)
DA14N: J13.75 U1.B6(DA14N)
DA14P: J13.73 U1.A6(DA14P)
DA15N: J13.69 U1.B7(DA15N)
DA15P: J13.67 U1.A7(DA15P)
DAC_DACCLK: C4.1 R15.2 U1.A12(DACCLKP)
DAC_DACCLKC: C3.1 R15.1 U1.A11(DACCLKN)
DAC_FIFO_OSTR: C2.1 R5.2 U1.A9(OSTRP)
DAC_FIFO_OSTRC: C1.1 R5.1 U1.B9(OSTRN)
DAC_RESET: C47.1 R46.1 SW1.3 SW1.4 U1.N10(RESETB)
DACCLK: R62.2 R66.1 R155.1 U2.20(U1N)
DACCLKC: R63.2 R67.1 R154.1 U2.19(U1P)
DATACLK-N: J13.117 SJP10.2(Pin2)
DATACLK-P: J13.115 SJP9.2(Pin2)
DATACLKN: SJP12.2(Pin2) U1.G1(DATACLKN)
DATACLKP: SJP11.2(Pin2) U1.G2(DATACLKP)
DB0N: J13.166 U1.P7(DB0N)
DB0P: J13.164 U1.N7(DB0P)
DB1N: J13.160 U1.P6(DB1N)
DB1P: J13.158 U1.N6(DB1P)
DB2N: J13.154 U1.P5(DB2N)
DB2P: J13.152 U1.N5(DB2P)
DB3N: J13.148 U1.P4(DB3N)
DB3P: J13.146 U1.N4(DB3P)
DB4N: J13.142 U1.P3(DB4N)
DB4P: J13.140 U1.N3(DB4P)
DB5N: J13.136 U1.P2(DB5N)
DB5P: J13.134 U1.N2(DB5P)
DB6N: J13.130 U1.P1(DB6N)
DB6P: J13.128 U1.N1(DB6P)
DB7N: J13.124 U1.M1(DB7N)
DB7P: J13.122 U1.M2(DB7P)
DB8N: J13.112 U1.M3(DB8N)
DB8P: J13.110 U1.M4(DB8P)
DB9N: J13.106 U1.L1(DB9N)
DB9P: J13.104 U1.L2(DB9P)
DB10N: J13.100 U1.L3(DB10N)
DB10P: J13.98 U1.L4(DB10P)
DB11N: J13.94 U1.K1(DB11N)
DB11P: J13.92 U1.K2(DB11P)
DB12N: J13.88 U1.K3(DB12N)
DB12P: J13.86 U1.K4(DB12P)
DB13N: J13.82 U1.J1(DB13N)
DB13P: J13.80 U1.J2(DB13P)
DB14N: J13.76 U1.J3(DB14N)
DB14P: J13.74 U1.J4(DB14P)
DB15N: J13.70 U1.H3(DB15N)
DB15P: J13.68 U1.H4(DB15P)
DCLK-N: SJP10.1(Pin1) SJP12.1(Pin1)
DCLK-P: SJP9.1(Pin1) SJP11.1(Pin1)
DCLKN: SJP10.3(Pin3) SJP12.3(Pin3)
DCLKP: SJP9.3(Pin3) SJP11.3(Pin3)
EXT_LFN: C52.1 C55.1 U2.41(EXT_LFN)
EXT_LFP: C55.2 R48.1 U2.40(EXT_LFP)
EXTIO: C37.1 TP2.1(TP) U1.G12(EXTIO)
FIFO-OSTR: C100.1 R68.2 R71.1 U2.17(U2N)
FIFO-OSTRC: C99.1 R69.2 R72.1 U2.16(U2P)
FIFO_ISTRN: J13.178 U1.H1(ISTRN)
FIFO_ISTRP: J13.176 U1.H2(ISTRP)
FIFO_OSTR: R89.2 R90.1 R152.1 U6.16(/Y1)
FIFO_OSTRC: R91.2 R92.1 R149.1 U6.15(Y1)
FPGA_CLKOUT2_N: J13.33 R93.1
FPGA_CLKOUT2_P: J13.31 R88.1
FPGA_CLKOUTN: J13.118 R117.2
FPGA_CLKOUTP: J13.116 R116.2
GC_+6.0VDC: C143.1 C144.1 J13.1 J13.2 J13.3 J13.4 JP10.3(Pin3)
IO_LOGIC: C51.1 C94.1 C98.1 C138.2 C140.1 C142.1 C250.1 JP2.1(Pin1) JP3.1(Pin1) R46.2 R73.1 R74.1 R83.1 R135.1 R136.1 R137.1 TP25.1(TP) U1.L12(IOVDD2) U3.4(VCCIO) U4.1(DIR2) U4.7(VCCA) U4.10(DIR1) U5.7(VCCA) U5.10(DIR1) U9.14(VCC) U10.5(VCC) U20.4(OUT)
IOUTA1: C281.2 C284.1 L41.2 R112.1 U1.B14(IOUT1P)
IOUTA2: C278.2 C281.1 L40.2 R98.1 U1.C14(IOUT1N)
IOUTB1: C269.2 C272.1 L36.2 R97.1 U1.F14(IOUT2P)
IOUTB2: C272.2 C275.1 L37.2 R96.1 U1.E14(IOUT2N)
IOUTC1: C263.2 C266.1 L34.2 R94.1 U1.J14(IOUT3P)
IOUTC2: C261.2 C263.1 L31.2 R41.1 U1.K14(IOUT3N)
IOUTD1: C251.2 C255.1 L27.2 R35.1 U1.N14(IOUT4P)
IOUTD2: C255.2 C258.1 L29.2 R33.1 U1.M14(IOUT4N)
PARITYN: J13.172 U1.P8(PARITYN)
PARITYP: J13.170 U1.N8(PARITYP)
PLLAVDD: C48.1 C49.1 FB1.1 TP26.1(TP) U1.C11(PLLAVDD) U1.D11(PLLAVDD)
SCLK: JP9.1 U1.P9(SCLK)
SDENB: JP12.1 U1.P10(SDENB)
SDIO: JP13.1 U1.P11(SDIO)
SDO: JP8.1 U1.P12(SDO)
SLEEP: JP3.2(Pin2) U1.N11(SLEEP)
SPI_CLK: R85.2 U2.24(SPI_CLK)
SPI_LE: R139.2 U2.25(SPI_LE)
SPI_MISO: R140.2 U2.22(SPI_MISO)
SPI_MOSI: R138.2 U2.23(SPI_MOSI)
SYNCN: R157.2 U1.B8(SYNCN)
SYNCP: R156.2 U1.A8(SYNCP)
TCXO_VCC: C178.1 C181.1 C182.1 FB25.1 R165.2 U16.9(VDD) U17.8(VDD)
TEST: TP4.1(TP) U1.L11(TESTMODE)
TXENABLE: JP2.2(Pin2) U1.N9(TXENABLE)
USB RESET: C50.1 SW2.3 SW2.4 U3.19(RESET)
VBB: R70.2 U6.6(VBB)
N24210609: C253.2 C254.1 L28.1 R6.2 R7.1 R104.1
N26666012: R44.1 U1.H12(RBIAS)
N26793352: C34.1 R43.2
N26794794: C35.1 R43.1 R133.1
N26951427: R25.1 T2.4(secondary_dot) T9.6(Primary_Dot)
N26951636: R20.1 T2.6(secondary) T9.4(Primary)
N26951698: C262.2 C265.1 L32.1 R21.2 R22.1 R106.1
N26961459: R34.1 T3.4(secondary_dot) T10.6(Primary_Dot)
N26961634: R32.2 R34.2
N26961668: R28.1 T3.6(secondary) T10.4(Primary)
N26961730: C271.2 C274.1 L35.1 R29.2 R30.1 R108.1
N26965899: C280.2 C283.1 L39.1 R37.2 R38.1 R110.1
N27066000: R44.2 R45.1
N27118781: C265.2 C268.1 L33.1 R23.1 R100.2 R107.1
N27125590: C274.2 C277.1 L38.1 R31.1 R101.2 R109.1
N27129848: C283.2 C286.1 L42.1 R39.1 R102.2 R111.1
N27288441: R79.2 U3.2(D4)
N27288443: C95.1 J14.2(D-) U3.16(USBDM)
N27288450: C92.1 C93.1 FB14.1 U3.20(VCC)
N27288471: R80.2 U3.9(D5)
N27288510: R81.2 U3.10(D6)
N27288614: C97.1 U3.17(3V3OUT)
N27288630: C96.1 J14.3(D+) U3.15(USBDP)
N27288689: R75.1 U4.8(A1) U9.2(1A)
N27288797: R75.2 U3.1(D0)
N27288876: R76.2 U3.5(D1)
N27289021: R77.2 U3.3(D2)
N27289053: R82.2 U3.6(D7)
N27299600: R78.1 U5.9(A2)
N27358249: R16.1 T1.4(secondary_dot) T8.6(Primary_Dot)
N27358251: R13.2 R16.2
N27379986: R42.1 T4.4(secondary_dot) T11.6(Primary_Dot)
N27396936: R4.1 T1.6(secondary) T8.4(Primary)
N27404153: R36.1 T4.6(secondary) T11.4(Primary)
N27685853: R7.2 R99.1
N27688076: R22.2 R100.1
N27690605: R30.2 R101.1
N27692844: R38.2 R102.1
N27760065: C76.1 C77.1 C78.1 C79.1 C80.1 C81.1 FB9.2 U2.26(VCC_OUT) U2.29(VCC_OUT) U2.32(VCC_OUT)
N27760104: C65.1 C66.1 FB5.2 U2.47(VCC_IN_PRI)
N27760106: C64.2 U2.38(REG_CAP2)
N27760178: C180.1 FB25.2 JP7.1
N27760241: C177.1 R95.1 U17.5(OUT)
N27760265: C53.1 J9.1(CENTER) R49.2
N27760429: C75.2 U2.4(REG_CAP1)
N27760435: JP4.3(Pin3) R51.2 R103.2
N27760437: C86.1 C87.1 FB12.2 U2.8(VCC_OUT)
N27760441: JP5.2(Pin2) U2.31(REF_SEL)
N27760496: C82.1 C83.1 FB10.2 U2.21(VCC_OUT)
N27760516: C73.1 C74.1 FB8.2 U2.1(VCC_IN_SEC)
N27760568: R61.2 R65.1 R116.1 R129.2 U2.9(U3P)
N27760578: C177.2 R166.2 R167.2 U2.3(SEC_REF+)
N27760635: R164.2 R165.1 TP14.1(TP) U16.8(EN) U17.1(REF)
N27760767: R60.2 R64.1 R117.1 R130.1 U2.10(U3N)
N27760883: R55.2 U2.30(TESTOUTA)
N27760967: C52.2 R48.2
N27760969: JP6.2(Pin2) U2.12(~{PWRDWN})
N27760997: C67.1 C68.1 FB6.2 U2.5(VCC1_PLL)
N27761158: C88.1 C89.1 FB13.1 U2.18(VCC_OUT)
N27761194: D1.1(ANODE) R52.2
N27761235: R52.1 U2.37(PLL_LOCK)
N27761514: R54.2 U2.6(U4P)
N27761516: R58.2 U2.7(U4N)
N27761629: C63.2 U2.48(VBB)
N27792689: C1.2 R122.2 R149.2
N27792693: C2.2 R123.2 R152.2
N27795123: C4.2 R125.2 R155.2
N27795145: C3.2 R124.2 R154.2
N27836250: J18.1 JP10.1(Pin1) TP12.1(TP)
N27836254: D2.1(ANODE) R143.1
N27959634: C165.1 FB31.1 L25.2 R148.2 U11.4(FB1)
N27964126: L25.1 U11.6(SW1)
N27965290: R148.1 R151.2 U11.5(DEF_1)
N27972790: C166.1 C167.1 FB30.1 L26.2 R150.2
N27972794: C166.2 R150.1 R153.2 U11.1(ADJ2)
N28017911: C162.1 U12.5(NR/FB)
N28017929: C145.1 C164.1 R147.1 U12.4(OUT)
N28017933: C163.1 R146.2 U12.1(EN) U12.2(IN)
N28058738: C133.1 C169.1 C234.1 FB31.3 R126.2 R145.2 R146.1 U13.1(IN) U13.3(EN)
N29123763: R9.1 T1.5(secondary_ct)
N29143306: R12.1 T2.5(secondary_ct)
N29165572: R14.1 T3.5(secondary_ct)
N29179841: R18.1 T4.5(secondary_ct)
N29448574: R36.2 R40.1
N29464199: R20.2 R24.1
N29945616: R133.2 U1.D12(PLLLF)
N30016149: C240.1 R126.1 U22.1(IN) U22.3(EN)
N30175128: C146.1 C244.1 C245.1 FB34.1 R128.2 R257.2 U13.5(OUT)
N30185572: C149.1 C246.1 C247.1 R127.1 R221.2 U22.5(OUT)
N30679143: C138.1 JP11.2 JP11.4 R134.1 R135.2 U20.5(NR/FB)
N30742942: JP11.1 R137.2
N30744213: JP11.3 R136.2
N30812023: R76.1 U4.9(A2) U9.12(4A)
N30837851: R85.1 U4.5(B1)
N30839067: R138.1 U4.4(B2)
N30879489: R139.1 U5.5(B1)
N30880109: R140.1 U5.4(B2)
N30892277: R84.1 U9.3(1Y)
N30900342: R74.2 R80.1 U9.5(2A)
N30908653: R86.1 U9.6(2Y)
N30910378: R79.1 R83.2 U9.13(4~{OE}) U10.1(OE)
N30914286: R82.1 U9.8(3Y)
N30924628: JP13.2 R87.2 U10.2(A)
N30955591: R81.1 U10.4(Y)
N30963273: R73.2 R77.1 U5.8(A1)
N30997791: JP9.2 R84.2
N30998469: JP12.2 R86.2
N31553936: R87.1 U9.11(4Y)
N32018373: JP8.2 U9.9(3A)
N33970284: R221.1 R315.2 U22.4(NR/FB)
N33977043: R257.1 R316.2 U13.4(NR/FB)
N34116776: C116.1 U15.6(NR)
N34116835: R168.2 R170.1 U15.3(FB/SNS)
N34123238: FB35.1 R127.2 R128.1
N34173216: R105.2 T8.1(Secondary_Dot)
N34173251: R104.2 T8.3(Secondary)
N34173344: C254.2 C259.1 L30.1 R10.1 R99.2 R105.1
N34173621: R107.2 T9.1(Secondary_Dot)
N34173656: R106.2 T9.3(Secondary)
N34174309: R109.2 T10.1(Secondary_Dot)
N34174344: R108.2 T10.3(Secondary)
N34174546: R111.2 T11.1(Secondary_Dot)
N34174581: R110.2 T11.3(Secondary)
N34195362: R131.1 U6.19(S1)
N34195366: C100.2 R206.1 U6.3(IN)
N34195397: C54.2 R70.1 R206.2 R207.1
N34195475: C99.2 R207.2 U6.4(/IN)
N34209596: J20.1(CENTER) R122.1
N34209604: J21.1(CENTER) R123.1
N34210478: J22.1(CENTER) R124.1
N34210481: J23.1(CENTER) R125.1
N34222239: J10.1(CENTER) R121.1
N34226368: J11.1(CENTER) R120.1
N34231598: J12.1(CENTER) R129.1
N34231946: J15.1(CENTER) R130.2
N34233040: J19.1(CENTER) U2.14(~{SYNC})
N34251384: C84.1 C85.1 FB11.2 U2.11(VCC_OUT)
N34259421: C252.2 C256.1 L27.1 L28.2
N34259427: C256.2 C257.1 L29.1 L30.2
N34269055: C260.2 C264.1 L31.1 L32.2
N34269061: C264.2 C267.1 L33.2 L34.1
N34269953: C270.2 C273.1 L35.2 L36.1
N34269959: C273.2 C276.1 L37.1 L38.2
N34270526: C279.2 C282.1 L39.2 L40.1
N34270532: C282.2 C285.1 L41.1 L42.2
N34305091: R95.2 U16.5(OUT)
N34315833: F3.1 JP10.2(Pin2) Q3.1(D1) Q3.2(D2) Q3.5(D5) Q3.6(D6) Q3.8(D8) U21.5(VIN)
N34315835: C152.1 C153.1 F3.2 FB20.2 Q3.4(S4) Q3.7(S7)
N34320644: Q3.3(G3) U21.4(GATE)
N34325133: L26.1 U11.10(SW2)
N34334652: J13.177 R157.1
N34334661: J13.175 R156.1

Not connected (* = marked no-connect by the designer): J13 5* 6* 7* 8* 9* 10* 11* 12* 13* 14* 15* 16* 17* 18* 19* 20* 21* 22* 23* 24* 25* 26* 27* 28* 30* 32* 34* 36* 37* 38* 39* 40* 41* 42* 43* 44* 45* 46* 47* 48* 49* 50* 51* 52* 53* 54* 55* 56* 57* 58* 59* 60* 61* 62* 63* 64* 169* 171*; J14 4(ID)*; T1 2(primary_ct)*; T2 2(primary_ct)*; T3 2(primary_ct)*; T4 2(primary_ct)*; U2 13(AUXOUT)* 27(U0P)* 28(U0N)* 33(TEST_MODE)*; U3 8(NC1)* 12(PWREN)* 13(RD)* 14(WR)* 22(TXE)* 23(RXF)* 24(NC2)* 27(OSCI)* 28(OSCO)*; U6 9(Y2)* 10(/Y2)* 12(NC)* 21(Y0)* 22(/Y0)*; U21 1(NC1)* 3(NC3)*

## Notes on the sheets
sheet 1
- NOTES:
- 1)  DNI = DO NOT INSTALL
sheet 2
- Place as close
  to the DAC as possible.
sheet 5
- ***DCLK-P/N are topside traces
sheet 6
- CLK
- DATA
- CTRL_LE
- OE
- SDEN
- SDIO
- SDOB
- U20 Configuration
  JP7
  Default open (+3.3V)
  1-2:  51.1K // 82K = 31.5K (+2.5V)
  3-4:  51.1K // 19.6K = 14K (+1.8V)
- 74AVC2T245
- 74LVC125A
- 74LVC1G126
- OE    DIR    OPERATION
- OE      A           Y
- OE      A          Y
- L      L         B -> A
- L      H           H
- H      H         H
- L      H         A -> B
- L      L           L
- H      L          L
- H      X         ISOLATION
- H      X          Z
- L      X           Z
sheet 7
- VCC_IN (+5V to +6V)
- To use Step Down Converter only (DNI LDO U12 ):
  Install R145
  DNI R146, R147
  Change R148 to 820K
  Change R151 to 180K
- For DAC34SH84EVM:
  Change R150 to 215K
  Change R221 and R257 to 232K
  DNI R128
  Install R126, R127
